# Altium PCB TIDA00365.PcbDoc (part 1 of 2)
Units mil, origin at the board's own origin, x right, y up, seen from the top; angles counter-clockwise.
Board outline 2520 x 2690 mil, 4 copper layers (Top Layer, Mid Layer, GND Layer, Bottom Layer), stack 69.2 mil thick; 170 components, 86 nets, 427 pads, 370 vias.
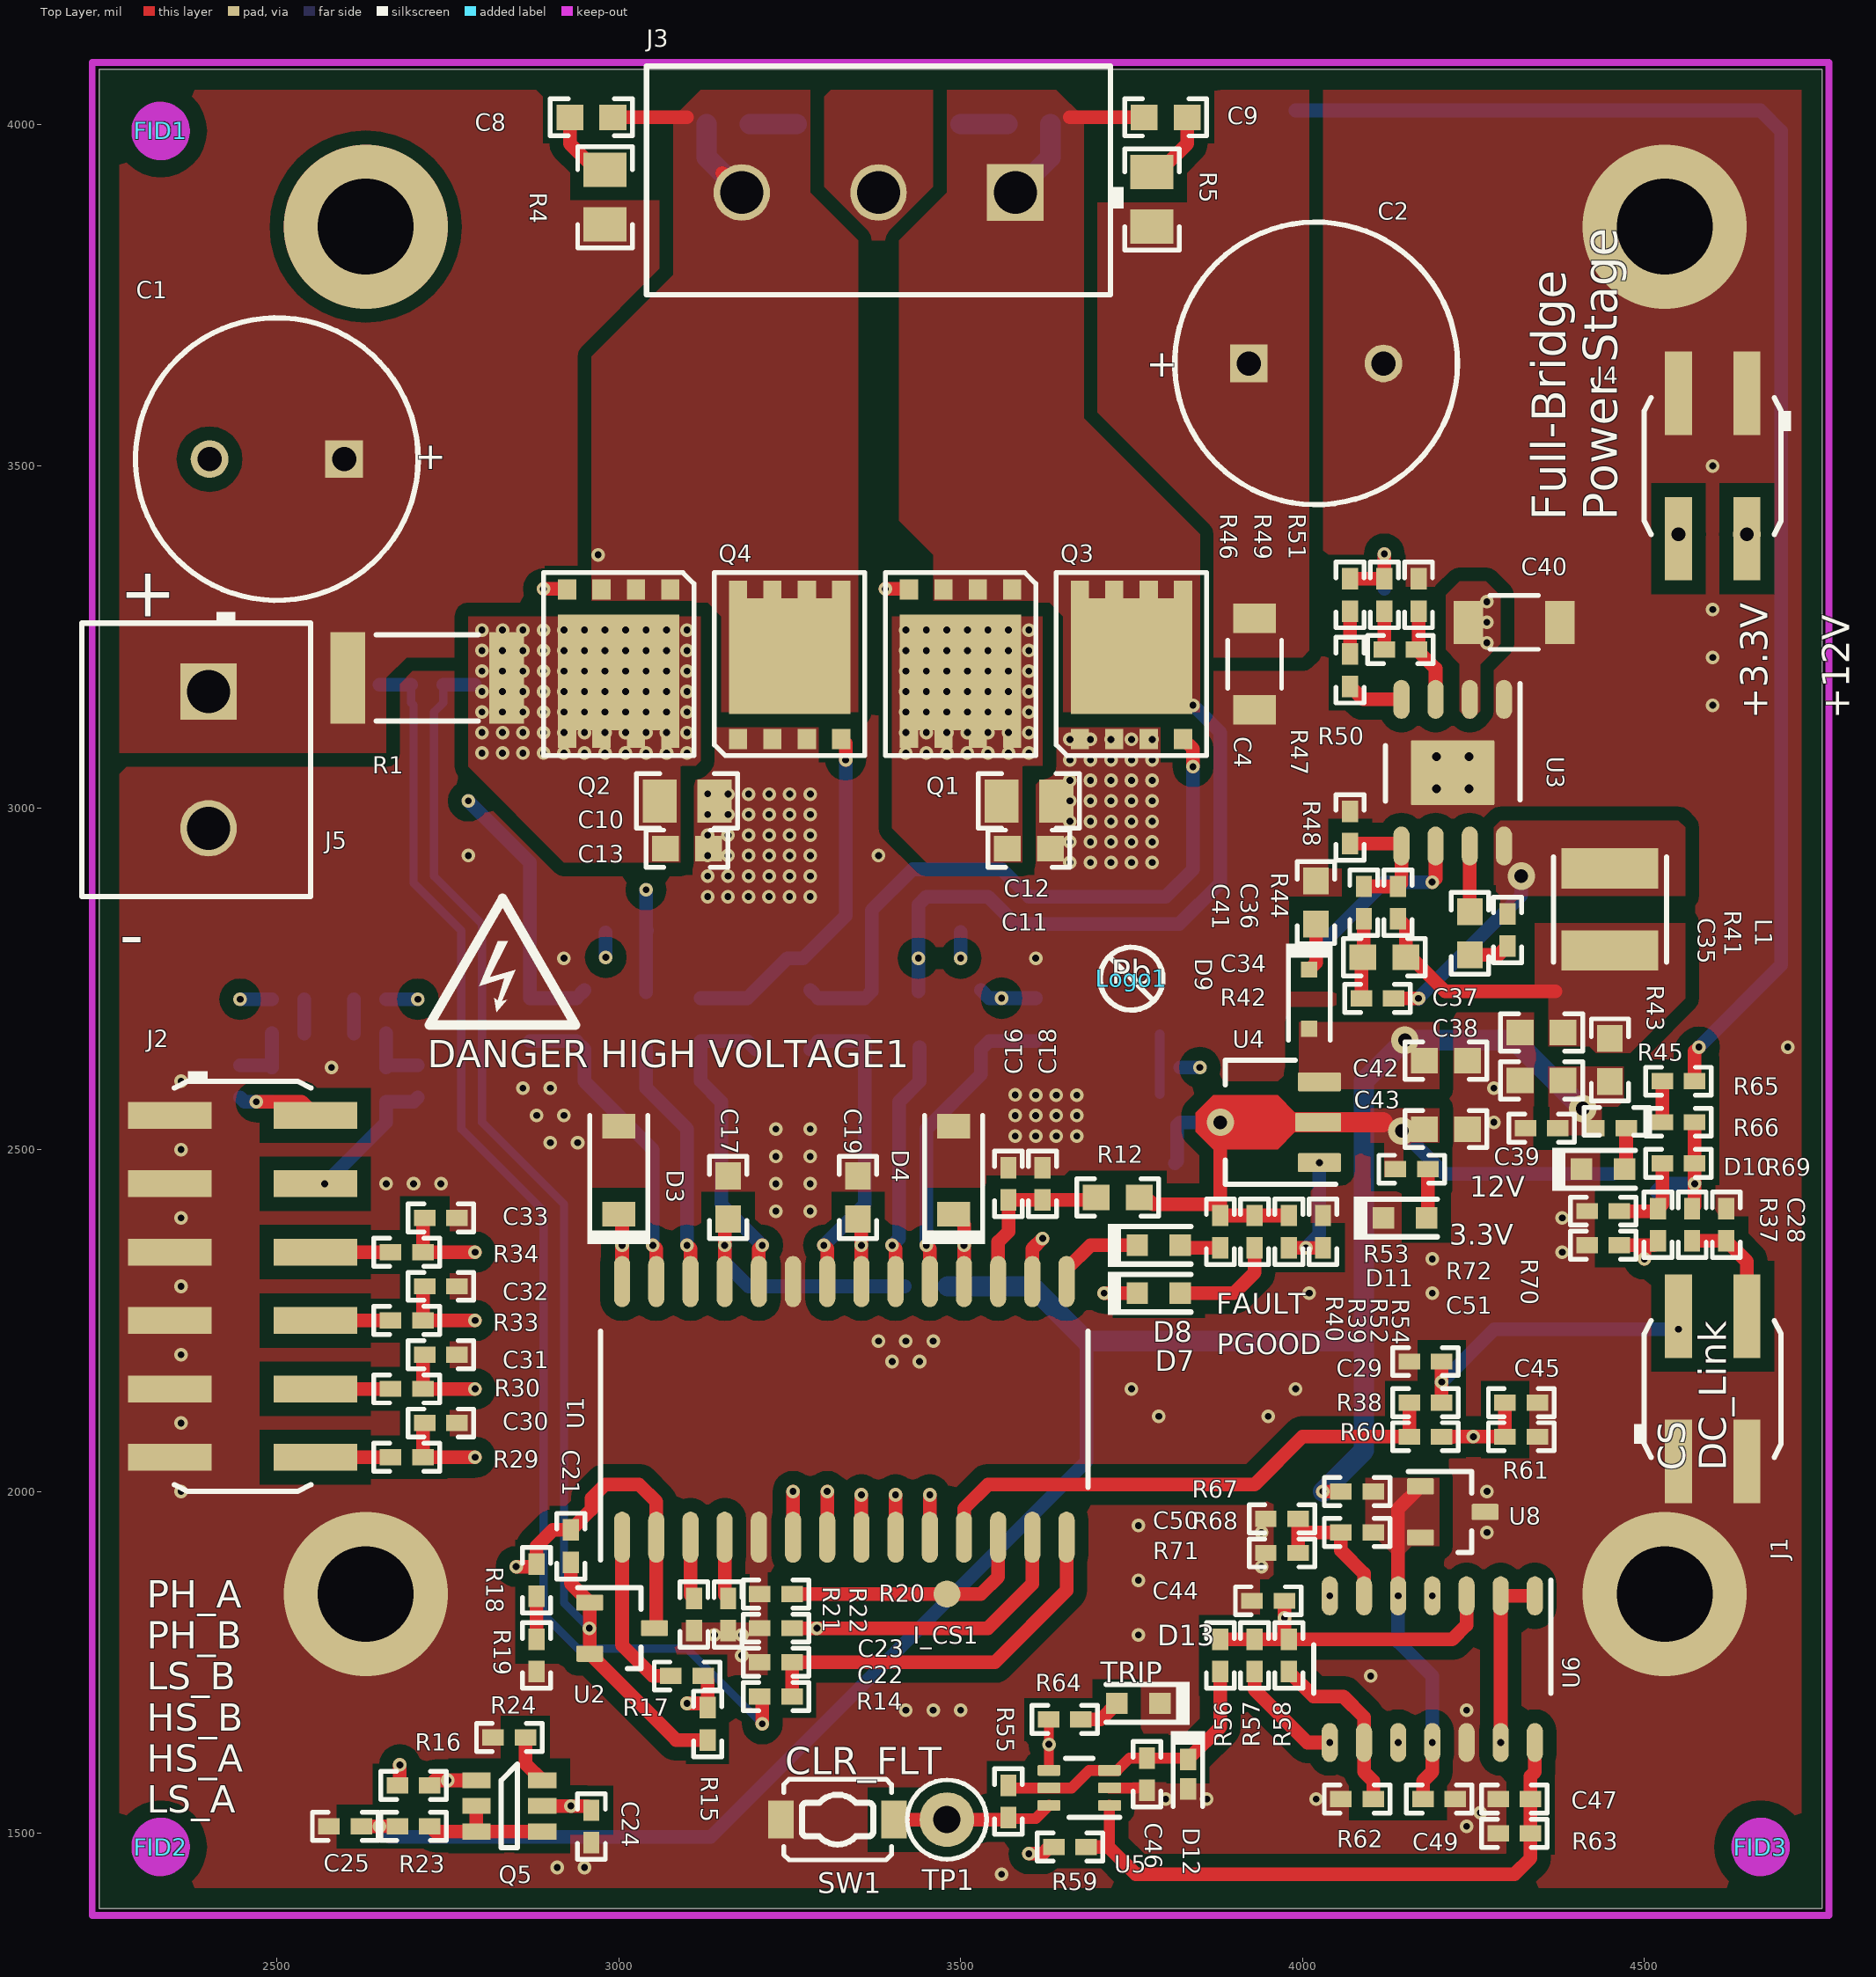
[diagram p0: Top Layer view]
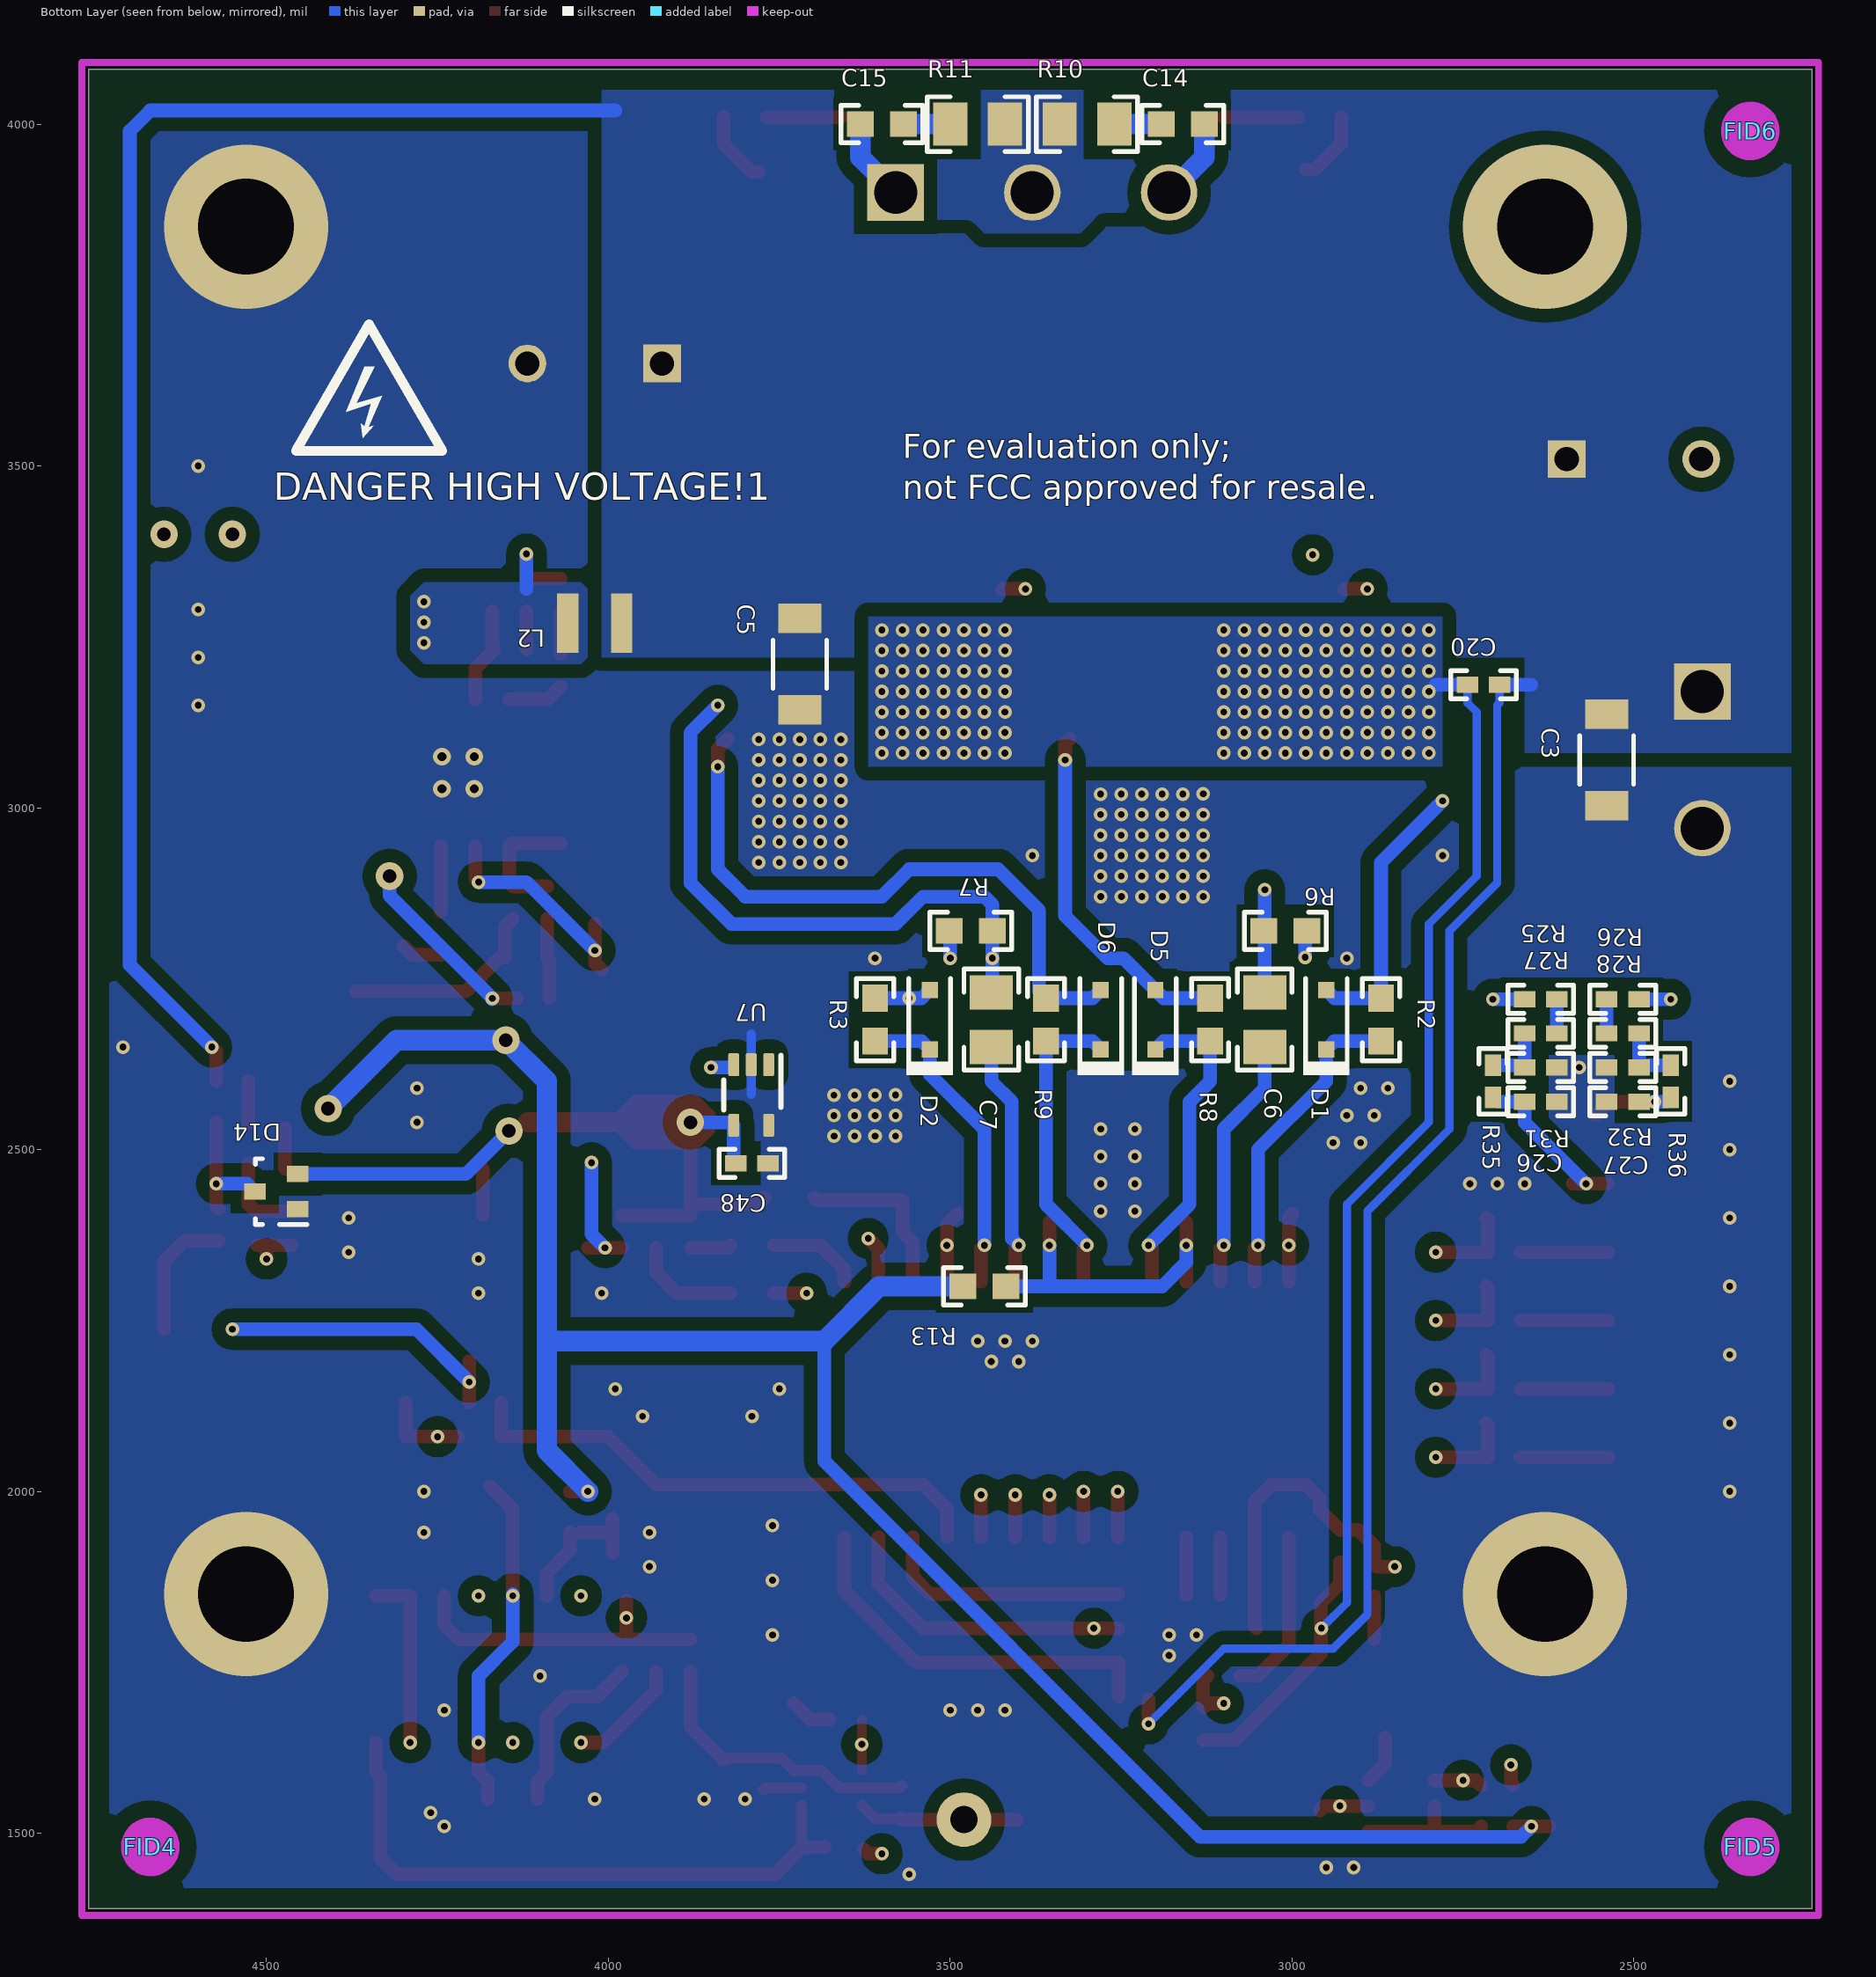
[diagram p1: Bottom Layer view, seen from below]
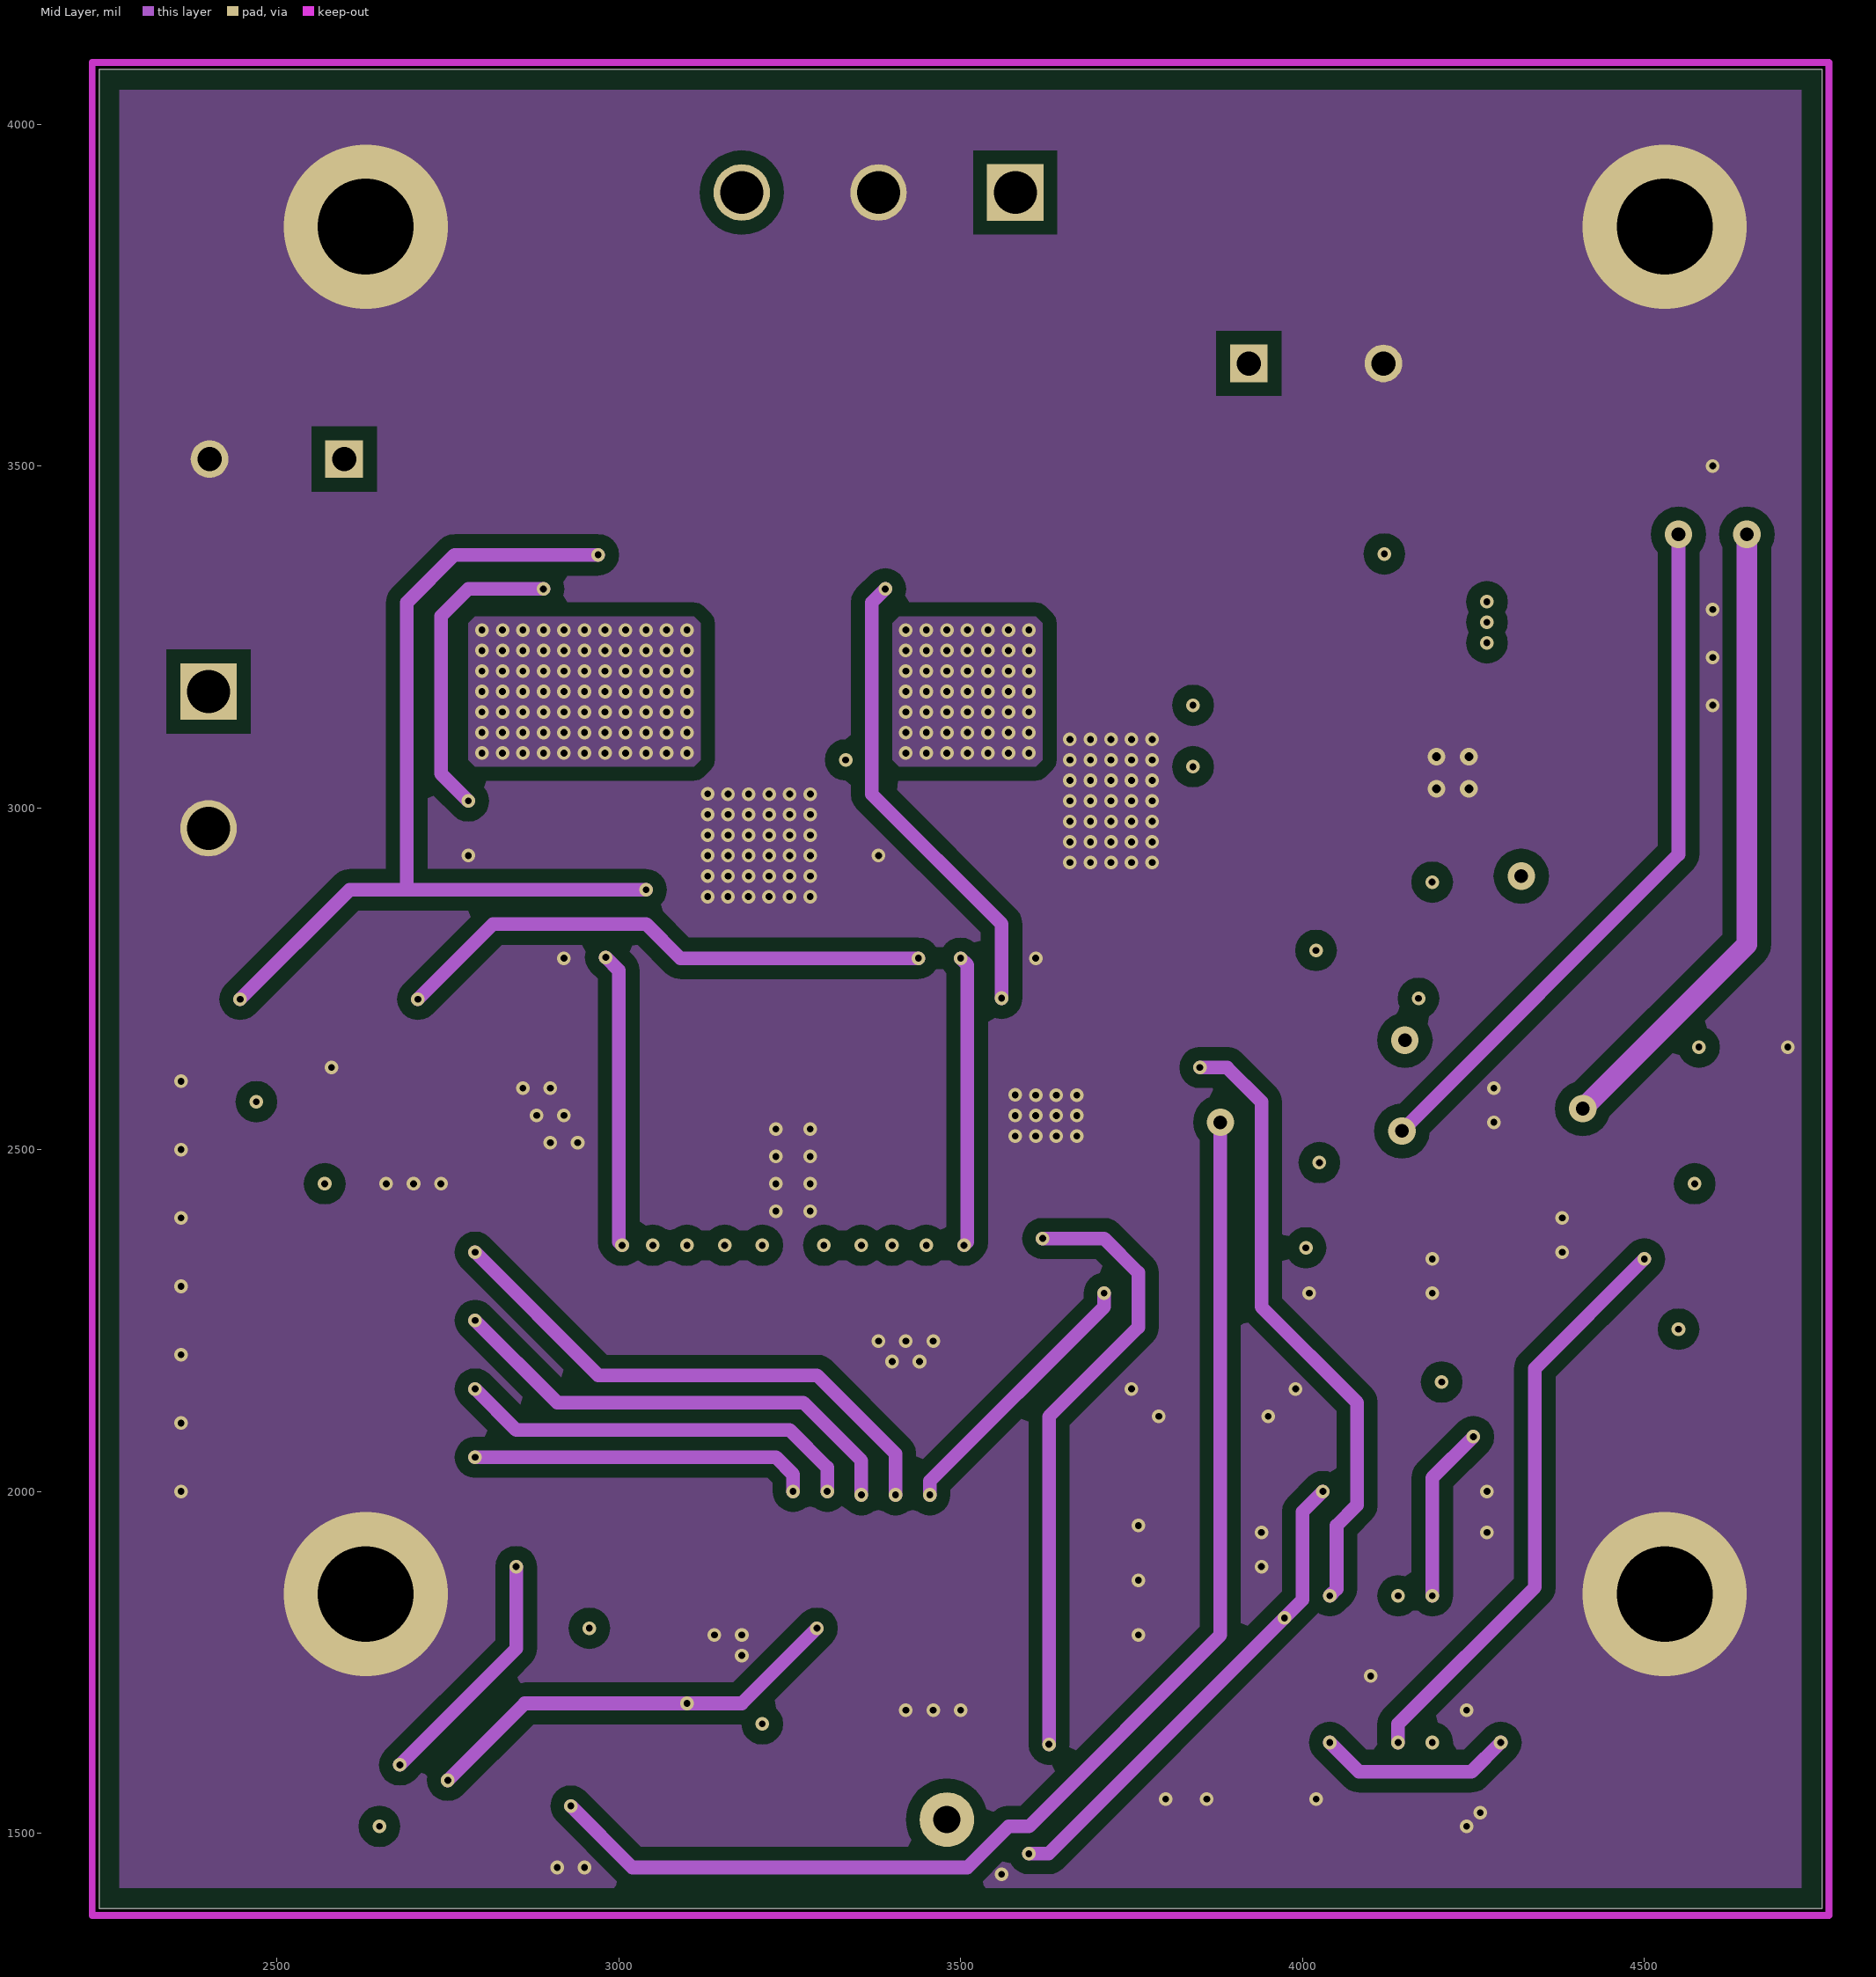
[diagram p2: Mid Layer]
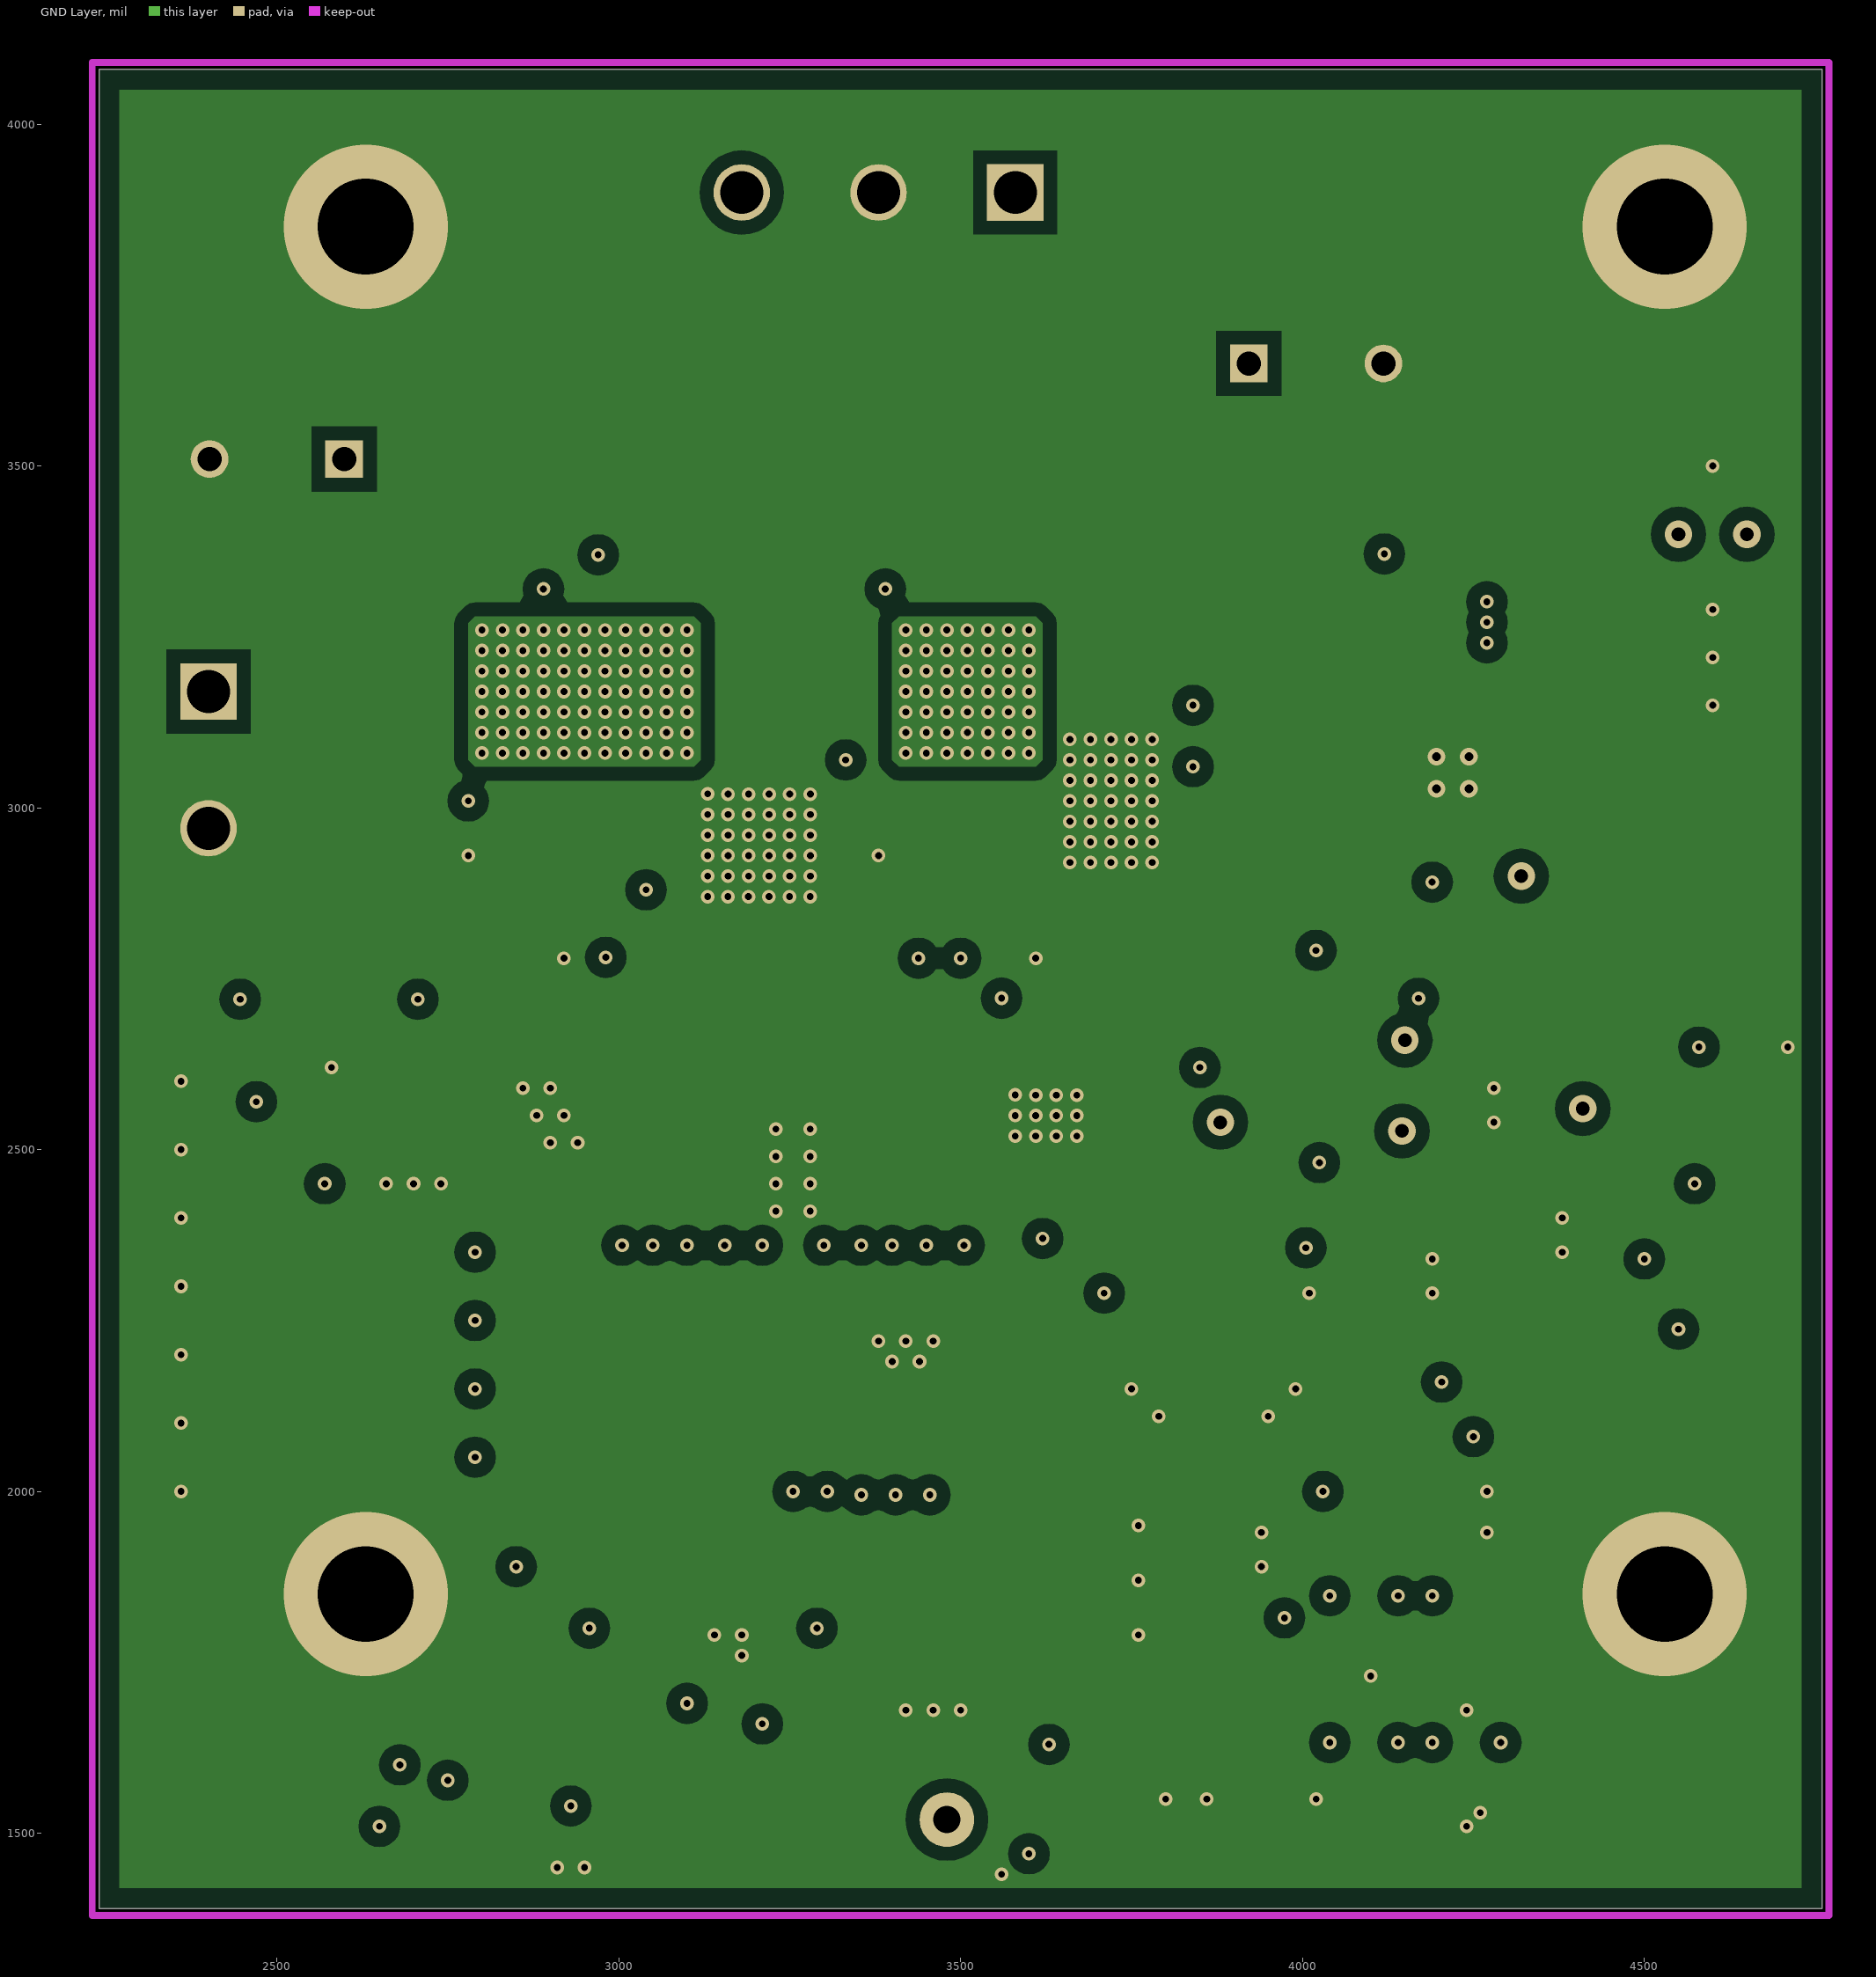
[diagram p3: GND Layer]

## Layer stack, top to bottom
Top Solder: solder mask 0.4, Solder Resist, Dk 3.5
Top Layer: signal copper 2.8
Dielectric: prepreg 12, FR-4, Dk 4.2
Mid Layer: signal copper 2.8
Dielectric: core 34, FR-4, Dk 4.2
GND Layer: signal copper 2.8
Dielectric: prepreg 12, FR-4, Dk 4.2
Bottom Layer: signal copper 2.8
Solder Side: solder mask 0.4, Solder Resist, Dk 3.5

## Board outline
2240,1390 2240,4080 4760,4080 4760,1390

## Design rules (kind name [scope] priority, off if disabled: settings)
AcuteAngle [All] p1: minimum=4.50000000000000E+0001 checktracksonly=FALSE
AssemblyTestPointUsage [All] p1: valid=2
Clearance Clearance_Keepouts [((IsTrack Or IsArc) And Not InPoly) And IsFree and IsKeepOut vs ((IsTrack Or IsArc) And Not InPoly) And IsFree and IsKeepOut] p1: gap=10
Clearance Clearance_BoardEdge_MountingHoles [OnCopper and InComponentClass('Mounting Holes') vs IsKeepOut] p2: gap=10
Clearance Clearance_BoardEdge_Poly [OnCopper and InPoly vs IsKeepOut] p3: gap=25
Clearance Clearance_BoardEdge [OnCopper and Not InComponentClass('Logo') and not InComponentClass('FiducialMark') and not InRegion(1000,500,4000,800) and Not IsKeepout vs IsKeepOut] p4: gap=25
Clearance Clearance_Poly [InPolygon] p5: gap=20
Clearance [All] p6: gap=8
ComponentClearance ComponentClearance_MountingHoles_FiducialMarks [InComponentClass('Mounting Holes') vs InComponentClass('FiducialMark')] p1: gap=20 collisioncheckmode=3 verticalgap=10 showdistances=FALSE
ComponentClearance ComponentClearance_Shunt [InComponentClass('Header') vs InComponentClass('Shunt')] p2: gap=0 collisioncheckmode=3 verticalgap=0 showdistances=FALSE
ComponentClearance ComponentClearance_Logo [InComponentClass('Logo')] p3: gap=10 collisioncheckmode=3 verticalgap=10 showdistances=FALSE
ComponentClearance ComponentClearance_ScrewToNut [(HasFootprint('NY PMS 440 0025 PH')) vs (HasFootprint('Keystone_1902C'))] p4: gap=5 collisioncheckmode=3 verticalgap=10 showdistances=FALSE
ComponentClearance ComponentClearance_MountingHoles [InComponentClass('Mounting Holes')] p5: gap=20 collisioncheckmode=3 verticalgap=100000 showdistances=FALSE
ComponentClearance ComponentClearance_SmallPassives [HasFootprint('0201*') or HasFootprint('0402*') or HasFootprint('0508') or HasFootprint('0603*') or HasFootprint('0612') or HasFootprint('0805*') or HasFootprint('0815*') or HasFootprint('0830*') or HasFootprint('1206*') or HasFootprint('1210*') or HasFootprint('1808*') or HasFootprint('1812*') or HasFootprint('1825*') or HasFootprint('2010*') or HasFootprint('2220*') or HasFootprint('2225*') or HasFootprint('2512*') or HasFootprint('2728*') or HasFootprint('3518*') vs HasFootprint('0201*') or HasFootprint('0402*') or HasFootprint('0508') or HasFootprint('0603*') or HasFootprint('0612') or HasFootprint('0805*') or HasFootprint('0815*') or HasFootprint('0830*') or HasFootprint('1206*') or HasFootprint('1210*') or HasFootprint('1808*') or HasFootprint('1812*') or HasFootprint('1825*') or HasFootprint('2010*') or HasFootprint('2220*') or HasFootprint('2225*') or HasFootprint('2512*') or HasFootprint('2728*') or HasFootprint('3518*')] p6: gap=20 collisioncheckmode=3 verticalgap=10 showdistances=FALSE
ComponentClearance ComponentClearance_THtoSMT [IsThruComponent vs IsSMTComponent] p7: gap=20 collisioncheckmode=3 verticalgap=30 showdistances=FALSE
ComponentClearance ComponentClearance_THtoTH [IsThruComponent vs IsThruComponent] p8: gap=20 collisioncheckmode=3 verticalgap=30 showdistances=FALSE
ComponentClearance [All] p9: gap=25 collisioncheckmode=3 verticalgap=10 showdistances=FALSE
DiffPairsRouting [All] p1: maxlimit=100 minlimit=10 mostfreqgap=10 toplayer_minwidth=15 toplayer_maxwidth=15 toplayer_prefwidth=15 midlayer1_minwidth=15 midlayer1_maxwidth=15 midlayer1_prefwidth=15 midlayer2_minwidth=15 midlayer2_maxwidth=15 midlayer2_prefwidth=15 bottomlayer_minwidth=15 bottomlayer_maxwidth=15 bottomlayer_prefwidth=15 maxuncoupledlength=1000
FabricationTestPointUsage TestPointUsage [All] p1: valid=2 allowmultiple=FALSE
FabricationTestpoint Testpoint [All] p1: side=3 testpointundercomponent=TRUE minsize=40 maxsize=100 preferedsize=60 minholesize=0 maxholesize=40 preferedholesize=32 testpointgrid=1 allowsidetop=TRUE allowsidebottom=TRUE usegrid=TRUE gridtolerance=0.01
FanoutControl Fanout_LCC [IsLCC] p1: bgadir=Out bgaviamode=Centered fanoutstyle=Auto fanoutdirection=Alternating viagrid=1 // Fanout_LCC (Default Rule)
FanoutControl Fanout_BGA [IsBGA] p2: bgadir=Out bgaviamode=Centered fanoutstyle=Auto fanoutdirection=Alternating viagrid=1 // Fanout_BGA (Default Rule)
FanoutControl Fanout_Default [All] p4: bgadir=Out bgaviamode=Centered fanoutstyle=Auto fanoutdirection=Alternating viagrid=1 // Fanout_Default (Default Rule)
FanoutControl Fanout_Small [(CompPinCount < 5)] p5: bgadir=Out bgaviamode=Centered fanoutstyle=Auto fanoutdirection=OutThenIn viagrid=1 // Fanout_Small (Default Rule)
Height [All] p1: minheight=0 maxheight=1100 prefheight=500
HoleSize [All] p1: absolutevalues=TRUE maxlimit=251 minlimit=8 maxpercent=80.000 minpercent=20.000
MinimumAnnularRing MinimumAnnularRing_ThermalPadVias [IsVia and InAnyComponent] p1: minimumring=6
MinimumAnnularRing [All] p2: minimumring=4
MinimumSolderMaskSliver MinimumSolderMaskSliver_Logo [InComponentClass('Logo') vs InComponentClass('Logo')] p1: minsoldermaskwidth=0.7
MinimumSolderMaskSliver [All] p2: minsoldermaskwidth=0
PlaneConnect [All] p1: planeconnectstyle=Relief reliefexpansion=10 reliefentries=4 reliefconductorwidth=10 reliefairgap=10
PolygonConnect PolygonConnect_59 [All vs IsNamedPolygon('GND_L04_P043')] p1: connectstyle=Direct reliefconductorwidth=10 reliefentries=4 polygonreliefangle="90 Angle" airgapwidth=10
PolygonConnect PolygonConnect_58 [All vs IsNamedPolygon('PROT_VTH_L01_P044')] p2: connectstyle=Direct reliefconductorwidth=10 reliefentries=4 polygonreliefangle="90 Angle" airgapwidth=10
PolygonConnect PolygonConnect_57 [All vs IsNamedPolygon('NONET_L04_P125')] p3: connectstyle=Direct reliefconductorwidth=10 reliefentries=4 polygonreliefangle="90 Angle" airgapwidth=10
PolygonConnect PolygonConnect_56 [All vs IsNamedPolygon('NONET_L04_P127')] p4: connectstyle=Direct reliefconductorwidth=10 reliefentries=4 polygonreliefangle="90 Angle" airgapwidth=10
PolygonConnect PolygonConnect_55 [All vs IsNamedPolygon('HS_CSN_2_L03_P049')] p5: connectstyle=Direct reliefconductorwidth=10 reliefentries=4 polygonreliefangle="90 Angle" airgapwidth=10
PolygonConnect PolygonConnect_54 [All vs IsNamedPolygon('HS_CSN_2_L03_P048')] p6: connectstyle=Direct reliefconductorwidth=10 reliefentries=4 polygonreliefangle="90 Angle" airgapwidth=10
PolygonConnect PolygonConnect_53 [All vs IsNamedPolygon('HS_CSN_2_L02_P050')] p7: connectstyle=Direct reliefconductorwidth=10 reliefentries=4 polygonreliefangle="90 Angle" airgapwidth=10
PolygonConnect PolygonConnect_52 [All vs IsNamedPolygon('HS_CSN_2_L02_P051')] p8: connectstyle=Direct reliefconductorwidth=10 reliefentries=4 polygonreliefangle="90 Angle" airgapwidth=10
PolygonConnect PolygonConnect_51 [All vs IsNamedPolygon('NETC32_1_L01_P052')] p9: connectstyle=Direct reliefconductorwidth=10 reliefentries=4 polygonreliefangle="90 Angle" airgapwidth=10
PolygonConnect PolygonConnect_50 [All vs IsNamedPolygon('HS_CSN_2_L04_P053')] p10: connectstyle=Direct reliefconductorwidth=10 reliefentries=4 polygonreliefangle="90 Angle" airgapwidth=10
PolygonConnect PolygonConnect_49 [All vs IsNamedPolygon('HS_CSN_2_L04_P053')] p11: connectstyle=Direct reliefconductorwidth=10 reliefentries=4 polygonreliefangle="90 Angle" airgapwidth=10
PolygonConnect PolygonConnect_48 [All vs IsNamedPolygon('HS_CSN_2_L01_P054')] p12: connectstyle=Direct reliefconductorwidth=10 reliefentries=4 polygonreliefangle="90 Angle" airgapwidth=10
PolygonConnect PolygonConnect_47 [All vs IsNamedPolygon('PHASEB+_L01_P056')] p13: connectstyle=Direct reliefconductorwidth=10 reliefentries=4 polygonreliefangle="90 Angle" airgapwidth=10
PolygonConnect PolygonConnect_46 [All vs IsNamedPolygon('HS_CSN_2_L01_P057')] p14: connectstyle=Direct reliefconductorwidth=10 reliefentries=4 polygonreliefangle="90 Angle" airgapwidth=10
PolygonConnect PolygonConnect_45 [All vs IsNamedPolygon('HS_CSP_2_L01_P058')] p15: connectstyle=Direct reliefconductorwidth=10 reliefentries=4 polygonreliefangle="90 Angle" airgapwidth=10
PolygonConnect PolygonConnect_44 [All vs IsNamedPolygon('PHASEB+_L01_P056')] p16: connectstyle=Direct reliefconductorwidth=10 reliefentries=4 polygonreliefangle="90 Angle" airgapwidth=10
PolygonConnect PolygonConnect_43 [All vs IsNamedPolygon('PHASEB-_L01_P055')] p17: connectstyle=Direct reliefconductorwidth=10 reliefentries=4 polygonreliefangle="90 Angle" airgapwidth=10
PolygonConnect PolygonConnect_42 [All vs IsNamedPolygon('GND_L02_P079')] p18: connectstyle=Direct reliefconductorwidth=10 reliefentries=4 polygonreliefangle="90 Angle" airgapwidth=10
PolygonConnect PolygonConnect_41 [All vs IsNamedPolygon('GND_L04_P077')] p19: connectstyle=Direct reliefconductorwidth=10 reliefentries=4 polygonreliefangle="90 Angle" airgapwidth=10
PolygonConnect PolygonConnect_40 [All vs IsNamedPolygon('GND_L01_P115')] p20: connectstyle=Direct reliefconductorwidth=10 reliefentries=4 polygonreliefangle="90 Angle" airgapwidth=10
PolygonConnect PolygonConnect_39 [All vs IsNamedPolygon('HS_CSP_2_L04_P063')] p21: connectstyle=Direct reliefconductorwidth=10 reliefentries=4 polygonreliefangle="90 Angle" airgapwidth=10
PolygonConnect PolygonConnect_38 [All vs IsNamedPolygon('HS_CSP_2_L04_P063')] p22: connectstyle=Direct reliefconductorwidth=10 reliefentries=4 polygonreliefangle="90 Angle" airgapwidth=10
PolygonConnect PolygonConnect_37 [All vs IsNamedPolygon('HS_CSP_2_L04_P063')] p23: connectstyle=Direct reliefconductorwidth=10 reliefentries=4 polygonreliefangle="90 Angle" airgapwidth=10
PolygonConnect PolygonConnect_36 [All vs IsNamedPolygon('HS_CSN_2_L04_P072')] p24: connectstyle=Direct reliefconductorwidth=10 reliefentries=4 polygonreliefangle="90 Angle" airgapwidth=10
PolygonConnect PolygonConnect_35 [All vs IsNamedPolygon('HS_CSP_2_L01_P061')] p25: connectstyle=Direct reliefconductorwidth=10 reliefentries=4 polygonreliefangle="90 Angle" airgapwidth=10
PolygonConnect PolygonConnect_34 [All vs IsNamedPolygon('Mid Layer-No Net')] p26: connectstyle=Direct reliefconductorwidth=10 reliefentries=4 polygonreliefangle="90 Angle" airgapwidth=10
PolygonConnect PolygonConnect_33 [All vs IsNamedPolygon('NETC28_1_L01_P073')] p27: connectstyle=Direct reliefconductorwidth=10 reliefentries=4 polygonreliefangle="90 Angle" airgapwidth=10
PolygonConnect PolygonConnect_32 [All vs IsNamedPolygon('Bottom Layer-No Net 4')] p28: connectstyle=Direct reliefconductorwidth=10 reliefentries=4 polygonreliefangle="90 Angle" airgapwidth=10
PolygonConnect PolygonConnect_31 [All vs IsNamedPolygon('GND Layer-No Net')] p29: connectstyle=Direct reliefconductorwidth=10 reliefentries=4 polygonreliefangle="90 Angle" airgapwidth=10
PolygonConnect PolygonConnect_30 [All vs IsNamedPolygon('Top Layer-No Net 16')] p30: connectstyle=Direct reliefconductorwidth=10 reliefentries=4 polygonreliefangle="90 Angle" airgapwidth=10
PolygonConnect PolygonConnect_29 [All vs IsNamedPolygon('Top Layer-No Net 15')] p31: connectstyle=Direct reliefconductorwidth=10 reliefentries=4 polygonreliefangle="90 Angle" airgapwidth=10
PolygonConnect PolygonConnect_28 [All vs IsNamedPolygon('Top Layer-No Net 14')] p32: connectstyle=Direct reliefconductorwidth=10 reliefentries=4 polygonreliefangle="90 Angle" airgapwidth=10
PolygonConnect PolygonConnect_27 [All vs IsNamedPolygon('Top Layer-No Net 13')] p33: connectstyle=Direct reliefconductorwidth=10 reliefentries=4 polygonreliefangle="90 Angle" airgapwidth=10
PolygonConnect PolygonConnect_26 [All vs IsNamedPolygon('NETL5_1_L01_P067')] p34: connectstyle=Direct reliefconductorwidth=10 reliefentries=4 polygonreliefangle="90 Angle" airgapwidth=10
PolygonConnect PolygonConnect_25 [All vs IsNamedPolygon('+12V_L01_P064')] p35: connectstyle=Direct reliefconductorwidth=10 reliefentries=4 polygonreliefangle="90 Angle" airgapwidth=10
PolygonConnect PolygonConnect_24 [All vs IsNamedPolygon('+12V_L01_P074')] p36: connectstyle=Direct reliefconductorwidth=10 reliefentries=4 polygonreliefangle="90 Angle" airgapwidth=10
PolygonConnect PolygonConnect_23 [All vs IsNamedPolygon('Bottom Layer-No Net 3')] p37: connectstyle=Direct reliefconductorwidth=10 reliefentries=4 polygonreliefangle="90 Angle" airgapwidth=10
PolygonConnect PolygonConnect_22 [All vs IsNamedPolygon('Bottom Layer-No Net 2')] p38: connectstyle=Direct reliefconductorwidth=10 reliefentries=4 polygonreliefangle="90 Angle" airgapwidth=10
PolygonConnect PolygonConnect_21 [All vs IsNamedPolygon('Bottom Layer-No Net 1')] p39: connectstyle=Direct reliefconductorwidth=10 reliefentries=4 polygonreliefangle="90 Angle" airgapwidth=10
PolygonConnect PolygonConnect_20 [All vs IsNamedPolygon('Bottom Layer-No Net')] p40: connectstyle=Direct reliefconductorwidth=10 reliefentries=4 polygonreliefangle="90 Angle" airgapwidth=10
PolygonConnect PolygonConnect_19 [All vs IsNamedPolygon('Bottom Layer-No Net 1')] p41: connectstyle=Direct reliefconductorwidth=10 reliefentries=4 polygonreliefangle="90 Angle" airgapwidth=10
PolygonConnect PolygonConnect_18 [All vs IsNamedPolygon('GND_L03_P078')] p42: connectstyle=Direct reliefconductorwidth=10 reliefentries=4 polygonreliefangle="90 Angle" airgapwidth=10
PolygonConnect PolygonConnect_17 [All vs IsNamedPolygon('GND_L03_P078')] p43: connectstyle=Direct reliefconductorwidth=10 reliefentries=4 polygonreliefangle="90 Angle" airgapwidth=10
PolygonConnect PolygonConnect_16 [All vs IsNamedPolygon('GND_L03_P078')] p44: connectstyle=Direct reliefconductorwidth=10 reliefentries=4 polygonreliefangle="90 Angle" airgapwidth=10
PolygonConnect PolygonConnect_15 [All vs IsNamedPolygon('GND_L03_P078')] p45: connectstyle=Direct reliefconductorwidth=10 reliefentries=4 polygonreliefangle="90 Angle" airgapwidth=10
PolygonConnect PolygonConnect_14 [All vs IsNamedPolygon('GND_L03_P078')] p46: connectstyle=Direct reliefconductorwidth=10 reliefentries=4 polygonreliefangle="90 Angle" airgapwidth=10
PolygonConnect PolygonConnect_13 [All vs IsNamedPolygon('NETC32_1_L04_P065')] p47: connectstyle=Direct reliefconductorwidth=10 reliefentries=4 polygonreliefangle="90 Angle" airgapwidth=10
PolygonConnect PolygonConnect_12 [All vs IsNamedPolygon('NETL5_1_L01_P067')] p48: connectstyle=Direct reliefconductorwidth=10 reliefentries=4 polygonreliefangle="90 Angle" airgapwidth=10
PolygonConnect PolygonConnect_11 [All vs IsNamedPolygon('+3V3_L01_P045')] p49: connectstyle=Direct reliefconductorwidth=10 reliefentries=4 polygonreliefangle="90 Angle" airgapwidth=10
PolygonConnect PolygonConnect_10 [All vs IsNamedPolygon('+3V3_L01_P045')] p50: connectstyle=Direct reliefconductorwidth=10 reliefentries=4 polygonreliefangle="90 Angle" airgapwidth=10
PolygonConnect PolygonConnect_9 [All vs IsNamedPolygon('NETC32_1_L04_P065')] p51: connectstyle=Direct reliefconductorwidth=10 reliefentries=4 polygonreliefangle="90 Angle" airgapwidth=10
PolygonConnect PolygonConnect_8 [All vs IsNamedPolygon('NETL5_1_L01_P067')] p52: connectstyle=Direct reliefconductorwidth=10 reliefentries=4 polygonreliefangle="90 Angle" airgapwidth=10
PolygonConnect PolygonConnect_7 [All vs IsNamedPolygon('NETC28_1_L01_P073')] p53: connectstyle=Direct reliefconductorwidth=10 reliefentries=4 polygonreliefangle="90 Angle" airgapwidth=10
PolygonConnect PolygonConnect_6 [All vs IsNamedPolygon('+3V3_L01_P045')] p54: connectstyle=Direct reliefconductorwidth=10 reliefentries=4 polygonreliefangle="90 Angle" airgapwidth=10
PolygonConnect PolygonConnect_5 [All vs IsNamedPolygon('+3V3_L01_P045')] p55: connectstyle=Direct reliefconductorwidth=10 reliefentries=4 polygonreliefangle="90 Angle" airgapwidth=10
PolygonConnect PolygonConnect_4 [All vs IsNamedPolygon('Top Layer-No Net 3')] p56: connectstyle=Direct reliefconductorwidth=10 reliefentries=4 polygonreliefangle="90 Angle" airgapwidth=10
PolygonConnect PolygonConnect_3 [All vs IsNamedPolygon('Top Layer-No Net 1')] p57: connectstyle=Direct reliefconductorwidth=10 reliefentries=4 polygonreliefangle="90 Angle" airgapwidth=10
PolygonConnect PolygonConnect_2 [All vs IsNamedPolygon('+12V_L01_P064')] p58: connectstyle=Direct reliefconductorwidth=10 reliefentries=4 polygonreliefangle="90 Angle" airgapwidth=10
PolygonConnect PolygonConnect_1 [All vs IsNamedPolygon('GND_L03_P078')] p59: connectstyle=Direct reliefconductorwidth=10 reliefentries=4 polygonreliefangle="90 Angle" airgapwidth=10
PolygonConnect [All] p60: connectstyle=Direct reliefconductorwidth=10 reliefentries=4 polygonreliefangle="90 Angle" airgapwidth=10
RoutingVias ThermalPadVias [IsVia and InAnyComponent] p1: holewidth=10 width=20 viastyle="Through Hole" minholewidth=5 minwidth=15 maxholewidth=25 maxwidth=45
RoutingVias [All] p2: holewidth=10 width=20 viastyle="Through Hole" minholewidth=5 minwidth=10 maxholewidth=200 maxwidth=300
SilkToBoardRegionClearance [Not ((IsComment or IsDesignator) And (Hide <> 'False')) and not InRegion(1000,500,4000,800)] p1:
SilkToSilkClearance SilkToSilkClearance_Pb-FreeLogo [(HasFootprint('Pb-Free_Overlay_Medium') OR HasFootprint('Pb-Free_Overlay_Small')) vs (HasFootprint('Pb-Free_Overlay_Medium') OR HasFootprint('Pb-Free_Overlay_Small'))] p1: silktosilkclearance=0
SilkToSilkClearance [All] p2: silktosilkclearance=0
SilkToSolderMaskClearance SilkToComonentPadClearance [IsPad and InAnycomponent] p1: minsilkscreentomaskgap=0 clearancetoexposedcopper=TRUE
SilkToSolderMaskClearance "Silk to Solder Mask Opening" [All] p2: minsilkscreentomaskgap=0 clearancetoexposedcopper=FALSE
SolderMaskExpansion [All] p1: expansion=1.97
Width [All] p1: maxlimit=200 minlimit=5 preferedwidth=20 checkconnectedcopper=TRUE
14 further rules are at their usual default settings.

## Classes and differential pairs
component class FiducialMark: FID1 FID2 FID3 FID4 FID5 FID6
component class TIDA00365_Interfaces: C3 C26 C27 C28 C30 C31 C32 C33 D1 D7 J2 J3 R8 R28 R29 R30 R31 R32 R33 R34 R35 R36 R37 R38 R39 R40 R53
component class "TIDA00365_Power Supply": 4V 12V C34 C35 C37 C38 C40 C41 C42 C43 C49 D1 D3 D11 J1 J4 L1 L2 R39 R41 R42 R43 R44 R45 R46 R47 R48 R49 R50 R52 R53 R54 U2 U4
component class "TIDA00365_Full Bridge": C2 C3 C4 C5 C6 C7 C9 C11 C12 C13 C14 C15 C16 C17 C18 C19 C20 C21 C22 C23 C24 C25 C45 C48 D1 D2 D3 D7 D11 D12 D14 I_CS1 Q1 Q2 Q3 Q4 Q5 R1 R2 R3 R4 R8 R12 R13 R15 R16 R20 R22 R23 R24 R34 R37 R39 R54 R58 R59 R62 R63 R65 R68 R70 U2 U7
component class TIDA00365_Protections: C1 C44 C45 C46 C47 C48 C49 C50 C51 D12 D13 D14 R1 R8 R17 R55 R56 R57 R58 R59 R60 R61 R62 R63 R65 R66 R68 R70 R71 R72 R? SW1 TP1 U5 U6 U7 U8
component class Header: J1 J4 J5
component class TIDA00365_Hardware: "DANGER HIGH VOLTAGE1" "DANGER HIGH VOLTAGE!1" FID1 FID2 FID3 FID4 FID5 FID6 Logo1 Logo2

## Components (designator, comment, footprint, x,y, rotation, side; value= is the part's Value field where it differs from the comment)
C1 "860040875005" WCAP-ATUL_1000x2500 2500,3510 r180 top
C2 "860040875005" WCAP-ATUL_1000x2500 4020,3650 r0 top
C3 "C3216X7S2A335M160AB" 1206_190 2540,3070 r270 bottom
C4 "C3216X7S2A335M160AB" 1206_190 3930,3210 r270 top
C5 "C3216X7S2A335M160AB" 1206_190 3720,3210 r270 bottom
C6 "C2012X7R2A104K125AA" 0805_HV 3040,2690 r90 bottom
C7 "C2012X7R2A104K125AA" 0805_HV 3440,2690 r90 bottom
C8 "06031C222JAT2A" 0603 2960,4010 r0 top
C9 "06031C222JAT2A" 0603 3800,4010 r180 top
C10 "C2012X7S2A105K125AB" 0805_HV 3100,3010 r0 top
C11 "06031C103KAT2A" 0603 3600,2940 r0 top
C12 "C2012X7S2A105K125AB" 0805_HV 3600,3010 r0 top
C13 "06031C103KAT2A" 0603 3100,2940 r0 top
C14 "06031C222JAT2A" 0603 3160,4000 r180 bottom
C15 "06031C222JAT2A" 0603 3600,4000 r0 bottom
C16 "885012205031" 0402#1 3570,2450 r90 top
C17 "885012106017" 0603 3160,2430 r270 top
C18 "C1005X7R1E104M050BB" 0402#1 3620,2450 r90 top
C19 "885012106017" 0603 3350,2430 r270 top
C20 "GRM155R72A472KA01D" 0402#1 2720,3180 r0 bottom
C21 "885012205055" 0402#1 2930,1920 r90 top
C22 "885012205055" 0402#1 3230,1750 r0 top
C23 "885012205055" 0402#1 3230,1800 r180 top
C24 "885012205031" 0402#1 2960,1510 r270 top
C25 "885012205031" 0402#1 2600,1510 r180 top
C26 "CC0402KRX7R9BB101" 0402#1 2636.38,2570 r0 bottom
C27 "CC0402KRX7R9BB101" 0402#1 2516.38,2570 r180 bottom
C28 "CC0402KRX7R9BB101" 0402#1 4620,2390 r270 top
C29 "CC0402KRX7R9BB101" 0402#1 4180,2190 r0 top
C30 "CC0402KRX7R9BB101" 0402#1 2740,2100 r0 top
C31 "CC0402KRX7R9BB101" 0402#1 2740,2200 r0 top
C32 "CC0402KRX7R9BB101" 0402#1 2740,2300 r0 top
C33 "CC0402KRX7R9BB101" 0402#1 2740,2400 r0 top
C34 "GRM188R72A332KA01D" 0603 4119.8,2781.3 r180 top
C35 "GRM188R72A104KA35D" 0603 4244.8,2816.3 r270 top
C36 "C1005X7R1E104M050BB" 0402#1 4089.8,2861.3 r90 top
C37 "GRM188R61E475KE11D" 0603 4349.8,2671.3 r180 top
C38 "GRM188R61E475KE11D" 0603 4349.8,2601.3 r180 top
C39 "C1005X7R1E104M050BB" 0402#1 4349.8,2531.3 r180 top
C40 "C3216X7S2A335M160AB" 1206_190 4309.8,3271.3 r0 top
C41 "C1608X5R1C105K" 0603 4019.8,2861.3 r90 top
C42 "C1608X5R1C105K" 0603 4210,2630 r0 top
C43 "C1608X5R1C105K" 0603 4210,2530 r0 top
C44 "C1005X7R1E104M050BB" 0402#1 3950,1840 r180 top
C45 "CC0402KRX7R9BB101" 0402#1 4320,2130 r0 top
C46 "885012205031" 0402#1 3772.65,1586.38 r270 top
C47 "CC0402KRX7R9BB101" 0402#1 4310,1550 r180 top
C48 "C1005X7R1E104M050BB" 0402#1 3790,2480 r180 bottom
C49 "885012205044" 0402#1 4200,1550 r0 top
C50 "885012105016" 0402#1 3970,1960 r180 top
C51 "CC0402KRX7R9BB101" 0402#1 4440,2360 r180 top
D1 "BAS316,115" sod-323 2950,2690 r90 bottom
D2 "BAS316,115" sod-323 3530,2690 r90 bottom
D3 "MMSZ5270BT1G" SOD-123 3000,2470 r90 top
D4 "MMSZ5270BT1G" SOD-123 3490,2470 r90 top
D5 "BAS316,115" sod-323 3200,2690 r90 bottom
D6 "BAS316,115" sod-323 3280,2690 r90 bottom
D7 "150060RS75000" WL-SMCW_RED 3790,2290 r0 top
D8 "150060RS75000" WL-SMCW_RED 3790,2360 r0 top
D9 "BAS316,115" sod-323 4010,2720 r270 top
D10 "150060GS75000" WL-SMCW_GREEN 4439.8,2471.3 r0 top
D11 "150060GS75000" WL-SMCW_GREEN 4150,2400 r0 top
D12 "BZT52C3V9T-7" SOD-523 3832.65,1586.38 r270 top
D13 "150060RS75000" WL-SMCW_RED 3760,1690 r180 top
D14 "BAV99W-7-F" SOT-323 4485.75,2438.6 r0 bottom
"DANGER HIGH VOLTAGE1" "DANGER HIGH VOLTAGE" IEC_HighVoltage_Small 2830,2770 r0 top
"DANGER HIGH VOLTAGE!1" "DANGER HIGH VOLTAGE" IEC_HighVoltage_Small 4350,3610 r180 bottom
FID1 "Fiducial" Fiducial6.4-20 2330,3990 r270 top
FID2 "Fiducial" Fiducial6.4-20 2330,1480 r270 top
FID3 "Fiducial" Fiducial6.4-20 4670,1480 r0 top
FID4 "Fiducial" Fiducial6.4-20 4670,1480 r180 bottom
FID5 "Fiducial" Fiducial6.4-20 2330,1480 r180 bottom
FID6 "Fiducial" Fiducial6.4-20 2330,3990 r180 bottom
I_CS1 "TESTPOINT" TP_SM_1MM 3480,1850 r90 top
J1 "61030421121" Wurth_61030421121 4600,2150 r90 top
J2 "61031221121" Wurth_61031221121 2450,2300 r0 top
J3 "691311500103" Wurth_691311500103 3380,3900 r180 top
J4 "61030421121" Wurth_61030421121 4600,3500 r270 top
J5 "691311500002" Wurth_691311500002 2400,3070 r270 top
L1 "74404041101" WE-LQS_4012 4449.8,2851.3 r270 top
L2 "74479887310" WE-PMI_1008 4020,3270 r0 bottom
Logo1 "Pb-Free Symbol" Pb-Free_Overlay_Small 3750,2750 r0 top
Logo2 "FCC disclaimer" FCC_disclaimer 1970,2060 r270 bottom
Q1 "CSD19534Q5A" TRANS_NexFET_Q5A 3500,3210 r270 top
Q2 "CSD19534Q5A" TRANS_NexFET_Q5A 3000,3210 r270 top
Q3 "CSD19534Q5A" TRANS_NexFET_Q5A 3750,3210 r90 top
Q4 "CSD19534Q5A" TRANS_NexFET_Q5A 3250,3210 r90 top
Q5 "DMMT5551-7-F" SOT-26 2840,1540 r0 top
R1 "CRA2512-FZ-R010ELF" 2512 2720,3190 r180 top
R2 "CRCW060347R0JNEA" 0603 2870,2690 r90 bottom
R3 "CRCW060347R0JNEA" 0603 3610,2690 r90 bottom
R4 "CRCW08052R70JNEA" 0805_HV 2980,3893.2 r270 top
R5 "CRCW08052R70JNEA" 0805_HV 3780,3890 r270 top
R6 "CRCW06033R00JNEA" 0603 3010,2820 r0 bottom
R7 "CRCW06033R00JNEA" 0603 3470,2820 r180 bottom
R8 "CRCW060347R0JNEA" 0603 3120,2690 r90 bottom
R9 "CRCW060347R0JNEA" 0603 3360,2690 r270 bottom
R10 "CRCW08052R70JNEA" 0805_HV 3300,4000 r0 bottom
R11 "CRCW08052R70JNEA" 0805_HV 3460,4000 r180 bottom
R12 "CRCW060310R0JNEA" 0603 3730,2430 r0 top
R13 "CRCW060310R0JNEA" 0603 3450,2300 r0 bottom
R14 "CRCW04021K50FKED" 0402#1 3230,1700 r180 top
R15 "CRCW04021K50FKED" 0402#1 3130,1660 r270 top
R16 "CRCW04020000Z0ED" 0402#1 2700,1570 r0 top
R17 "CRCW040223K2FKED" 0402#1 3100,1730 r0 top
R18 "CRCW0402180KJNED" 0402#1 2880,1870 r270 top
R19 "CRCW0402180KJNED" 0402#1 2880,1760 r90 top
R20 "CRCW040216K5FKED" 0402#1 3230,1850 r0 top
R21 "CRCW040210K0JNED" 0402#1 3110,1820 r90 top
R22 "CRCW040210K0JNED" 0402#1 3160,1820 r90 top
R23 "CRCW040224K0JNED" 0402#1 2700,1510 r180 top
R24 "CRCW040233K2FKED" 0402#1 2840,1640 r0 top
R25 "CRCW040249K9FKED" 0402#1 2636.38,2720 r0 bottom
R26 "CRCW040249K9FKED" 0402#1 2516.38,2720 r180 bottom
R27 "CRCW040249K9FKED" 0402#1 2636.38,2670 r180 bottom
R28 "CRCW040249K9FKED" 0402#1 2516.38,2670 r0 bottom
R29 "CRCW040222R0JNED" 0402#1 2690,2050 r0 top
R30 "CRCW040222R0JNED" 0402#1 2690,2150 r0 top
R31 "CRCW04023K32FKED" 0402#1 2636.38,2620 r0 bottom
R32 "CRCW04023K32FKED" 0402#1 2516.38,2620 r180 bottom
R33 "CRCW040222R0JNED" 0402#1 2690,2250 r0 top
R34 "CRCW040222R0JNED" 0402#1 2690,2350 r0 top
R35 "CRCW040222R0JNED" 0402#1 2706.38,2600 r90 bottom
R36 "CRCW040222R0JNED" 0402#1 2446.38,2600 r90 bottom
R37 "CRCW040222R0JNED" 0402#1 4570,2390 r90 top
R38 "CRCW040222R0JNED" 0402#1 4180,2130 r180 top
R39 "CRCW04021K20JNED" 0402#1 3930,2380 r90 top
R40 "CRCW04021K20JNED" 0402#1 3880,2380 r90 top
R41 "CRCW04023R00JNED" 0402#1 4299.8,2821.3 r90 top
R42 "CRCW040251K0JNED" 0402#1 4109.8,2721.3 r180 top
R43 "CRCW060310R0JNEA" 0603 4449.8,2631.3 r270 top
R44 "CRCW040220K0FKED" 0402#1 4139.8,2861.3 r270 top
R45 "CRCW04029K10JNED" 0402#2 4459.8,2541.3 r180 top
R46 "CRCW0402200KJNED" 0402#1 4069.8,3311.3 r270 top
R47 "CRCW0402200KJNED" 0402#1 4069.8,3201.3 r270 top
R48 "CRCW04022K26FKED" 0402#1 4069.8,2971.3 r270 top
R49 "CRCW040251K0JNED" 0402#1 4119.8,3311.3 r270 top
R50 "CRCW040251K0JNED" 0402#1 4143.43,3231.3 r0 top
R51 "CRCW04027K50JNED" 0402#1 4169.8,3311.3 r270 top
R52 "CRCW0402475RFKED" 0402#1 3980,2380 r90 top
R53 "CRCW0402820RJNED" 0402#1 4159.8,2471.3 r180 top
R54 "CRCW0402806RFKED" 0402#1 4030,2380 r270 top
R55 "CRCW040251K0JNED" 0402#1 3570,1546.38 r90 top
R56 "CRCW04021K20JNED" 0402#1 3880,1760 r90 top
R57 "CRCW040251K0JNED" 0402#1 3930,1760 r270 top
R58 "CRCW040251K0JNED" 0402#1 3980,1760 r270 top
R59 "CRCW0402100KJNED" 0402#1 3660,1480 r180 top
R60 "CRCW04023K24FKED" 0402#1 4180,2080 r0 top
R61 "CRCW040210K0FKED" 0402#1 4320,2080 r180 top
R62 "CRCW040251K0JNED" 0402#1 4080,1550 r180 top
R63 "CRCW040251K0JNED" 0402#1 4310,1500 r0 top
R64 "CRCW04021K80JNED" 0402#1 3652.28,1666.38 r0 top
R65 "CRCW040249K9FKED" 0402#1 4550,2600 r0 top
R66 "CRCW040249K9FKED" 0402#1 4550,2540 r180 top
R67 "CRCW04026K80JNED" 0402#1 4080,2000 r180 top
R68 "CRCW0402487KFKED" 0402#1 4080,1940 r0 top
R69 "CRCW04021K00FKED" 0402#1 4550,2480 r0 top
R70 "CRCW0402100RJNED" 0402#1 4520,2390 r90 top
R71 "CRCW0402100KFKED" 0402#1 3970,1910 r0 top
R72 "CRCW04023K09FKED" 0402#1 4440,2410 r0 top
SW1 "TL1015AF160QG" SW_TL1015AF160QG 3320,1520 r0 top
TP1 "5002" Keystone5002 3480,1520 r90 top
U1 "SM72295MAX/NOPB" DW0028A_N 3330,2120 r90 top
U2 "ATL431BQDBZR" DBZ0003A_N 3005,1800 r0 top
U3 "LM5018MRX/NOPB" DDA0008B_N 4219.8,3051.3 r270 top
U4 "LM317LIPK" PK0003A_N 3950,2540 r180 top
U5 "SN74LVC1G175DCKR" DCK0006A_N 3673.62,1566.38 r180 top
U6 "LM2901VQD" D0014A_N 4190,1740 r270 top
U7 "LMT89DCKR" DCK0005A_N 3791.11,2579.95 r270 bottom
U8 "TL431QDBZT" DBZ0003A_N 4220,1970 r0 top

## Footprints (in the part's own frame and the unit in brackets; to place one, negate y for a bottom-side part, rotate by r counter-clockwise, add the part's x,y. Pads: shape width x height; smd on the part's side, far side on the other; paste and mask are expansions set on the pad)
0402#1 [mm] "0402 from SM-752 data"
  rect 0.8x0.6 smd: 1(-0.6,0) 2(0.6,0)
  silkscreen extent -1.22,-0.52 1.22,0.52, body extent -0.55,-0.3 0.55,0.3, height 0.6
0402#2 [mm] "0402 from SM-752 data"
  rect 0.8x0.6 smd: 1(-0.346,0.254) 2(0.854,0.254)
  silkscreen extent -1.22,-0.52 1.22,0.52, body extent -0.55,-0.3 0.55,0.3, height 0.6
0603 [mm] "0603 from SM-752 data"
  rect 1x0.95 smd: 1(-0.8,0) 2(0.8,0)
  silkscreen extent -1.52,-0.69 1.52,0.69, body extent -0.87,-0.47 0.87,0.47, height 1
0805_HV [mil] "0805 with 30mil clearance between pads"
  rect 50x63 smd: 1(-40,0) 2(40,0)
  silkscreen extent -74,-40 74,40, body extent -43,-29 43,29, height 57
1206_190 [mm] "1206_190"
  rect 1.1x1.6 smd: 1(-1.7,0) 2(1.7,0)
  silkscreen extent -0.9,-1 0.9,1, body extent -1.75,-0.95 1.75,0.95, height 1.9
2512 [mm] "Chip Resistor, Body 6.3x3.2mm, IPC Medium Density"
  rect 1.3x3.4 smd: 1(-2.95,0) 2(2.95,0)
  silkscreen extent -1.9,-1.6 1.9,1.6, body extent -3.22,-1.67 3.22,1.67, height 0.71
D0014A_N [mm] "SOIC, 14-Leads, Body 8.7x3.9mm, Pitch 1.27mm, IPC Medium Density"
  oval 1.45x0.6 smd: 1(-2.725,3.81) 2(-2.725,2.54) 3(-2.725,1.27) 4(-2.725,0) 5(-2.725,-1.27) 6(-2.725,-2.54) 7(-2.725,-3.81) 8(2.725,-3.81) 9(2.725,-2.54) 10(2.725,-1.27) 11(2.725,0) 12(2.725,1.27) 13(2.725,2.54) 14(2.725,3.81)
  silkscreen extent -3.3,-4.4 0.9,4.4, body extent -3.02,-4.32 3.02,4.32, height 1.6
DBZ0003A_N [mm] "SOT23, 3-Leads, Body 2.9x1.3mm, Pitch 0.95mm, Lead Span 2.4mm, IPC Medium Density"
  rrect17% 1x0.6 smd: 1(-1.2,0.95) 2(-1.2,-0.95) 3(1.2,0)
  silkscreen extent -1.65,-1.5 0.7,1.5, body extent -1.26,-1.46 1.26,1.46, height 0.98
DCK0005A_N [mm] "SOT353, 5-Leads, Body 2x1.3mm, Pitch 0.65mm, Lead Span 2.1mm, IPC Medium Density"
  rrect25% 0.85x0.4 smd: 1(-1.125,0.65) 2(-1.125,0) 3(-1.125,-0.65) 4(1.125,-0.65) 5(1.125,0.65)
  silkscreen extent -1.48,-1.02 0.55,1.1, body extent -1.14,-1 1.14,1, height 0.95
DCK0006A_N [mm] "SOT23, 6-Leads, Body 2x1.3mm, Pitch 0.65mm, Lead Span 2.1mm, IPC Medium Density"
  rrect25% 0.85x0.4 smd: 1(-1.125,0.65) 2(-1.125,0) 3(-1.125,-0.65) 4(1.125,-0.65) 5(1.125,0) 6(1.125,0.65)
  silkscreen extent -1.5,-1.09 0.51,1.09, body extent -1.14,-1 1.14,1, height 0.95
DDA0008B_N [mm] "SOIC, 8-Leads, Body 4.9x3.9mm, Pitch 1.27mm, Exposed Pad, IPC Medium Density"
  rrect100% 1.45x0.6 smd: 1(-2.725,1.905) 2(-2.725,0.635) 3(-2.725,-0.635) 4(-2.725,-1.905) 5(2.725,-1.905) 6(2.725,-0.635) 7(2.725,0.635) 8(2.725,1.905)
  rrect4% 2.41x3.1 smd: 9(0,0)
  silkscreen extent -3.3,-2.5 1.05,2.5, body extent -2.98,-2.45 2.98,2.45, height 1.55
DW0028A_N [mm] "SOIC, 28-Leads, Body 17.9x7.5mm, Pitch 1.27mm, IPC Medium Density"
  oval 1.9x0.6 smd: 1(-4.75,8.255) 2(-4.75,6.985) 3(-4.75,5.715) 4(-4.75,4.445) 5(-4.75,3.175) 6(-4.75,1.905) 7(-4.75,0.635) 8(-4.75,-0.635) 9(-4.75,-1.905) 10(-4.75,-3.175) 11(-4.75,-4.445) 12(-4.75,-5.715) 13(-4.75,-6.985) 14(-4.75,-8.255) 15(4.75,-8.255) 16(4.75,-6.985) 17(4.75,-5.715) 18(4.75,-4.445) 19(4.75,-3.175) 20(4.75,-1.905) 21(4.75,-0.635) 22(4.75,0.635) 23(4.75,1.905) 24(4.75,3.175) 25(4.75,4.445) 26(4.75,5.715) 27(4.75,6.985) 28(4.75,8.255)
  silkscreen extent -5.6,-9.05 2.9,9.05, body extent -5.16,-8.95 5.16,8.95, height 2.54
FCC_disclaimer [mil]
Fiducial6.4-20 [mil]
  round 25 smd mask+26.87: 1(0,0)
  Top Layer keep-out circle w46.37: c0,0 r19.68
IEC_HighVoltage_Small [mil]
  silkscreen extent -107,-88 107,97
Keystone5002 [mil] "For Keystone 500x miniature loop terminals"
  round 80 hole 40: 1(0,0)
  silkscreen extent -58,-58 58,58, body extent -49,-49 49,49, height 182
Pb-Free_Overlay_Small [mil]
  silkscreen extent -46,-46 46,46
PK0003A_N [mm] "SOT89, 3-Leads, Body 4.5x2.5mm, Pitch 1.5mm, IPC Medium Density"
  rrect14% 1.6x0.7 smd: 1(-1.9,1.5) 3(-1.9,-1.5)
  rrect14% 1.7x0.7 smd: 2(-1.85,0)
  Top Layer region: -1,0.35 -0.35,1 2.05,1 2.7,0.35 2.7,-0.35 2.05,-1 -0.35,-1 -1,-0.35 -1.2,-0.35 -1.2,0.35
  silkscreen extent -2.5,-2.3 1.6,2.3, body extent -2.13,-2.25 1.96,2.25, height 1.6
SOD-123 [mm] "On Semi recommended land pattern"
  rect 0.915x1.22 smd: 1(-1.637,0) 2(1.637,0)
  silkscreen extent -2.74,-1.17 2.03,1.17, body extent -1.93,-0.9 1.93,0.9, height 1.35
sod-323 [mm] "NXP recommended land pattern"
  rect 0.6x0.6 smd paste-0.05: 1(-1.1,0) 2(1.1,0)
  silkscreen extent -2.06,-0.86 1.53,0.86, body extent -1.3,-0.67 1.3,0.68, height 1.1
SOD-523 [mm] "NXP Semiconductor recommended land pattern, nominal STEP model"
  rect 0.8x0.6 smd paste-0.05: 1(-0.55,0) 2(0.55,0)
  silkscreen extent -1.6,-0.64 1.2,0.63, body extent -0.8,-0.4 0.8,0.4, height 0.72
SOT-26 [mm] "SOT23, 6-Leads, Body 3.1x3.0mm (max), Pitch 0.95mm, IPC Medium Density based on Diodes Inc ap02002.pdf rev 29"
  rect 1.05x0.6 smd: 1(-1.225,0.95) 2(-1.225,0) 3(-1.225,-0.95) 4(1.225,-0.95) 5(1.225,0) 6(1.225,0.95)
  silkscreen extent -0.3,-1.55 0.3,1.55, body extent -1.5,-1.5 1.5,1.5, height 1.3
SOT-323 [mm] "Zetex recommended land pattern.  March 2007"
  rect 0.8x0.6 smd: 1(-0.8,0.65) 2(-0.8,-0.65) 3(0.8,0)
  silkscreen extent -1.14,-1.22 0.77,1.22, body extent -1.13,-1.13 1.12,1.12, height 1.13
SW_TL1015AF160QG [mm] "E-Switch"
  rect 0.95x1.4 smd: 1(-2.1,0) 2(2.1,0)
  silkscreen extent -2,-1.5 2,1.5, body extent -2.3,-1.5 2.3,1.5, height 2
TP_SM_1MM [mm] "1mm Test Point, SMT"
  round 1 smd paste-0.5: 1(0,0)
TRANS_NexFET_Q5A [mm] "TI recommended land pattern (nominal) M0139-01"
  rect 0.75x0.675 smd paste-0.1 mask+0.051: 1(-2.776,1.917) 2(-2.776,0.639) 3(-2.776,-0.639) 4(-2.776,-1.917)
  rect 0.655x0.675 smd paste-0.1 mask+0.051: 5(2.776,-1.917) 6(2.776,-0.639) 7(2.776,0.639) 8(2.776,1.917)
  rect 4.295x4.51 smd paste-2.2 mask+0.051: 9(0.301,0)
  silkscreen extent -3.4,-2.8 3.4,2.8, body extent -3.05,-2.5 3.05,2.5, height 1.11
WCAP-ATUL_1000x2500 [mm] "TH, 2-Leads, Dia 10mm, Pin Spacing 5mm"
  rect 1.4x1.4 hole 0.9: 1(-2.5,0)
  round 1.4 hole 0.9: 2(2.5,0)
  silkscreen extent -5.25,-5.25 5.25,5.25, body extent -5.21,-5.24 5.24,5.24, height 26.51
WE-LQS_4012 [mm] "SMD, 2-Leads, Body 3.7x4mm"
  rect 1.5x3.6 smd: 1(-1.525,0) 2(1.525,0)
  silkscreen extent -1.95,-2.1 1.95,2.1, body extent -1.95,-2.1 1.95,2.1, height 1.2
WE-PMI_1008 [mm] "WURTH"
  rect 0.8x2.2 smd: 1(-1,0) 2(1,0)
  body extent -1.35,-1.1 1.35,1.1, height 1
WL-SMCW_GREEN [mm] "WURTH"
  rect 0.8x0.8 smd: 1(-0.8,0) 2(0.8,0)
  silkscreen extent -1.9,-0.8 1.2,0.8, body extent -0.85,-0.45 0.85,0.45, height 0.8
WL-SMCW_RED [mm] "WURTH"
  rect 0.8x0.8 smd: 1(-0.8,0) 2(0.8,0)
  silkscreen extent -1.9,-0.8 1.2,0.8, body extent -0.85,-0.45 0.85,0.45, height 0.8
Wurth_61030421121 [mm] "Header, 2.54mm, 2x2, Gold, TH"
  rect 3.1x1 smd: 1(-2.7,1.27) 2(2.7,1.27) 3(-2.7,-1.27) 4(2.7,-1.27)
  silkscreen extent -2.54,-2.54 2.54,2.92, body extent -3.75,-2.54 3.75,2.54, height 9.6
Wurth_61031221121 [mm] "Header, 2.54mm, 6x2, Gold, TH"
  rect 3.1x1 smd: 1(-2.7,6.35) 2(2.7,6.35) 3(-2.7,3.81) 4(2.7,3.81) 5(-2.7,1.27) 6(2.7,1.27) 7(-2.7,-1.27) 8(2.7,-1.27) 9(-2.7,-3.81) 10(2.7,-3.81) 11(-2.7,-6.35) 12(2.7,-6.35)
  silkscreen extent -2.54,-7.62 2.54,8, body extent -3.75,-7.62 3.75,7.62, height 9.6
Wurth_691311500002 [mm] "Header (Shrouded), 5.08mm, 2x1, TH"
  rect 2.1x2.1 hole 1.6: 1(-2.54,0)
  round 2.1 hole 1.6: 2(2.54,0)
  silkscreen extent -5.5,-4.7 5.08,3.8, body extent -5.06,-4.7 5.1,3.8, height 12
Wurth_691311500103 [mm] "Header (Shrouded), 5.08mm, 3x1, TH"
  rect 2.1x2.1 hole 1.6: 1(-5.08,0)
  round 2.1 hole 1.6: 2(0,0) 3(5.08,0)
  Top Layer lines w0.1: 0.25,0 -0.25,0 ; 0,0.25 0,-0.25
  silkscreen extent -9.1,-4.7 8.62,3.8, body extent -8.62,-4.7 8.62,3.8, height 12

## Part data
C1 C2: "CAP, AL, 100 µF, 100 V, +/- 20%, 0.2 ohm, TH"
C3 C4 C5 C40: "CAP, CERM, 3.3 µF, 100 V, +/- 20%, X7S, 1206_190"
C6 C7: "CAP, CERM, 0.1 µF, 100 V, +/- 10%, X7R, 0805"
C8 C9 C14 C15: "CAP, CERM, 2200 pF, 100 V, +/- 5%, X7R, 0603"
C10 C12: "CAP, CERM, 1 µF, 100 V, +/- 10%, X7S, 0805"
C11 C13: "CAP, CERM, 0.01 µF, 100 V, +/- 10%, X7R, 0603"
C16 C24 C25 C46: "CAP, CERM, 0.01 µF, 16 V, +/- 10%, X7R, 0402"
C17 C19: "CAP, CERM, 1 µF, 16 V, +/- 20%, X5R, 0603"
C18 C36 C39 C44 C48: "CAP, CERM, 0.1 µF, 25 V, +/- 20%, X7R, 0402"
C20: "CAP, CERM, 4700 pF, 100 V, +/- 10%, X7R, 0402"
C21 C22 C23 C26 C27 C28 C29 C30 C31 C32 C33 C45 C47 C51: "CAP, CERM, 100 pF, 50 V, +/- 10%, X7R, 0402"
C34: "CAP, CERM, 3300 pF, 100 V, +/- 10%, X7R, 0603"
C35: "CAP, CERM, 0.1 µF, 100 V, +/- 10%, X7R, 0603"
C37 C38: "CAP, CERM, 4.7 µF, 25 V, +/- 10%, X5R, 0603"
C41 C42 C43: "CAP, CERM, 1 µF, 16 V, +/- 10%, X5R, 0603"
C49: "CAP, CERM, 1000 pF, 25 V, +/- 10%, X7R, 0402"
C50: "CAP, CERM, 0.1 µF, 16 V, +/- 20%, X5R, 0402"
D1 D2 D5 D6 D9: "Diode, Ultrafast, 100 V, 0.25 A, SOD-323"
D3 D4: "Diode, Zener, 91 V, 500 mW, SOD-123"
D7 D8 D13: "LED, Red, SMD"
D10 D11: "LED, Green, SMD"
D12: "Diode, Zener, 3.9 V, 300 mW, SOD-523"
D14: "Diode, Switching, 75 V, 0.15 A, SOT-323"
"DANGER HIGH VOLTAGE1" "DANGER HIGH VOLTAGE!1": library part IEC_HighVoltage, "IEC 61010-1 High Voltage Warning"
FID1 FID2 FID3 FID4 FID5 FID6: "Fiducial mark.  There is nothing to buy or mount."
I_CS1: library part TP_SM_1MM, "1mm Test Point, SMT"
J1 J4: "Header, 2.54mm, 2x2, Gold, SMT"
J2: "Header, 2.54mm, 6x2, Gold, SMT"
J3: "Header (Shrouded), 5.08mm, 3x1, Tin, TH"
J5: "Header (Shrouded), 5.08mm, 2x1, Tin, TH"
L1: "Inductor, Wirewound, Ferrite, 100 µH, 0.35 A, 1.697 ohm, SMD"
L2: "Inductor, Shielded Drum Core, Metal Composite, 10 µH, 0.35 A, 0.7 ohm, SMD"
Logo1: library part Pb-Free
Logo2: library part FCC_disclaimer, "FCC_disclaimer"
Q1 Q2 Q3 Q4: "MOSFET, N-CH, 100 V, 10 A, SON 5x6mm"
Q5: library part "DMMT5551-7-F, Diodes Inc.", "Transistor, Dual NPN, 160 V, 0.2 A, SOT-26"
R1: "RES, 0.01, 1%, 3 W, 2512"
R2 R3 R8 R9: "RES, 47, 5%, 0.1 W, 0603"
R4 R5 R10 R11: "RES, 2.7, 5%, 0.125 W, 0805"
R6 R7: "RES, 3.0, 5%, 0.1 W, 0603"
R12 R13 R43: "RES, 10, 5%, 0.1 W, 0603"
R14 R15: "RES, 1.50 k, 1%, 0.063 W, 0402"
R16: "RES, 0, 5%, 0.063 W, 0402"
R17: "RES, 23.2 k, 1%, 0.063 W, 0402"
R18 R19: "RES, 180 k, 5%, 0.063 W, 0402"
R20: "RES, 16.5 k, 1%, 0.063 W, 0402"
R21 R22: "RES, 10 k, 5%, 0.063 W, 0402"
R23: "RES, 24 k, 5%, 0.063 W, 0402"
R24: "RES, 33.2 k, 1%, 0.063 W, 0402"
R25 R26 R27 R28 R65 R66: "RES, 49.9 k, 1%, 0.063 W, 0402"
R29 R30 R33 R34 R35 R36 R37 R38: "RES, 22, 5%, 0.063 W, 0402"
R31 R32: "RES, 3.32 k, 1%, 0.063 W, 0402"
R39 R40 R56: "RES, 1.2 k, 5%, 0.063 W, 0402"
R41: "RES, 3.0, 5%, 0.063 W, 0402"
R42 R49 R50 R55 R57 R58 R62 R63: "RES, 51 k, 5%, 0.063 W, 0402"
R44: "RES, 20.0 k, 1%, 0.063 W, 0402"
R45: "RES, 9.1 k, 5%, 0.063 W, 0402"
R46 R47: "RES, 200 k, 5%, 0.063 W, 0402"
R48: "RES, 2.26 k, 1%, 0.063 W, 0402"
R51: "RES, 7.5 k, 5%, 0.063 W, 0402"
R52: "RES, 475, 1%, 0.063 W, 0402"
R53: "RES, 820, 5%, 0.063 W, 0402"
R54: "RES, 806, 1%, 0.063 W, 0402"
R59: "RES, 100 k, 5%, 0.063 W, 0402"
R60: "RES, 3.24 k, 1%, 0.063 W, 0402"
R61: "RES, 10.0 k, 1%, 0.063 W, 0402"
R64: "RES, 1.8 k, 5%, 0.063 W, 0402"
R67: "RES, 6.8 k, 5%, 0.063 W, 0402"
R68: "RES, 487 k, 1%, 0.063 W, 0402"
R69: "RES, 1.00 k, 1%, 0.063 W, 0402"
R70: "RES, 100, 5%, 0.063 W, 0402"
R71: "RES, 100 k, 1%, 0.063 W, 0402"
R72: "RES, 3.09 k, 1%, 0.063 W, 0402"
SW1: "Switch, Tactile, SPST-NO, 0.05A, 12V, SMT"
TP1: "Test Point, Miniature, White, TH"
U1: "Photovoltaic Full Bridge Driver, DW0028A"
U2: "2.5V Low Iq Adjustable Precision Shunt Regulator, DBZ0003A"
U3: "100V, 300mA Constant On-Time Synchronous Buck Regulator, DDA0008B"
U4: "3-Terminal Adjustable Regulator, PK0003A"
U5: "SINGLE D-TYPE FLIP-FLOP WITH ASYNCHRONOUS CLEAR, DCK0006A"
U6: "Quad Comparator, D0014A"
U7: "2.4V, 10µA, SC70, DSBGA Temperature Sensor, DCK0005A"
U8: "Adjustable Precision Shunt Regulator, 34 ppm / degC, 100 mA, -40 to 125 degC, 3-pin SOT-23 (DBZ), Green (RoHS & no Sb/Br)"

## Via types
v1: diameter 20, hole 10, Top Layer to Bottom Layer, 355 vias
v2: diameter 40, hole 20, Top Layer to Bottom Layer, 7 vias
v3: diameter 240, hole 140, Top Layer to Bottom Layer, 4 vias
v4: diameter 25.98, hole 12.99, Top Layer to Bottom Layer, tented top, 4 vias

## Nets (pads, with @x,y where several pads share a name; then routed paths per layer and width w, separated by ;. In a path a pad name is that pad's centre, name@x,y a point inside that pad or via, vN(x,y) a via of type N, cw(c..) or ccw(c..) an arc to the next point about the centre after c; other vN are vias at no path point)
+3V3: C24.1 C43.1 C48.1 D14.2 J4.4 Q5.5 R12.2 R39.2 R40.2 R52.2 R53.2 U4.2 U7.4 | length 4036.2
  Top Layer w20: Q5.5@2888.23,1540 v1(2930,1540) 2953.62,1540 C24.1@2960,1533.62 ; R12.2@3771.5,2430 3781.5,2420 3880,2420 ; v2(3880,2540) 3880,2420 ; R52.2@3980,2403.62 R39.2@3930,2403.62 R40.2@3880,2403.62 3880,2420
  Top Layer w30: v2(3880,2540) U4.2@4022.83,2540 4117.51,2540
  Mid Layer w20: v1(2930,1540) 3020,1450 3510,1450 3570,1510 3600,1510 3880,1790 v2(3880,2540) ; v2(4145.53,2527.27) 4550,2931.74 v2(4550,3400)
  Bottom Layer w20: C48.1@3813.62,2480 3816.7,2483.08 U7.4@3816.7,2535.66 3821.05,2540 v2(3880,2540) ; v2(4145.53,2527.27) 4208.6,2464.19 D14.2@4454.25,2464.19
+4V: C46.1 D12.1 R55.2 R56.1 U5.3 U5.5 | length 432.1
  Top Layer w16: R55.2@3570,1570 3573.62,1566.38 U5.5@3629.33,1566.38 3662.65,1566.38 3688.24,1591.97 U5.3@3717.91,1591.97 3729.21,1591.97 3747.24,1610 C46.1@3772.65,1610 D12.1@3834.62,1610
  Top Layer w20: D12.1@3832.65,1608.03 3834.62,1610 3880,1655.38 R56.1@3880,1736.38
+12V: C25.1 C38.1 C39.1 C42.1 C44.1 D9.2 J4.2 R13.2 R23.2 R43.2 R45.2 R56.2 R57.1 R58.1 R59.2 R67.2 U4.3 U6.3 | length 5339.6
  Top Layer w20: C25.1@2623.62,1510 v1(2650,1510) R23.2@2676.38,1510 ; v1(3600,1470) 3620,1470 R59.2@3626.38,1476.38 ; R56.2@3880,1783.62 R58.1@3980,1783.62 ; C44.1@3973.62,1840 v1(3973.62,1815) 3973.62,1790 R58.1@3980,1783.62 ; v1(4030,2000) R67.2@4056.38,2000 ; U6.3@4240,1847.28 4240,1804.45 4219.17,1783.62 R58.1@3980,1783.62
  Mid Layer w20: v1(3600,1470) 3628.62,1470 v1(3973.62,1815) 4000,1841.38 4000,1970 v1(4030,2000)
  Mid Layer w30: v2(4410,2560) 4650,2800 v2(4650,3400)
  Bottom Layer w20: v1(2650,1510) 2665.13,1494.87 3134.87,1494.87 3684.33,2044.33 3684.33,2220
  Bottom Layer w30: R13.2@3481.5,2300 3604.33,2300 3684.33,2220 4090,2220 ; v1(4030,2000) 4090,2060 4090,2220 ; v2(4410,2560) 4310,2660 v2(4150,2660) 4090,2600 4090,2220
/FAULT: D8.1 U1.15 | length 136
  Top Layer w20: U1.15@3655,2307.01 3655,2325 3690,2360 D8.1@3758.5,2360
BIN: R22.2 U1.4 | length 84.4
  Top Layer w20: R22.2@3155,1848.62 U1.4@3155,1932.99
BOUT: R38.2 R60.1 U1.11 | length 786.9
  Top Layer w20: U1.11@3505,1932.99 3505,1975 3540,2010 3930,2010 4000,2080 R60.1@4156.38,2080 R38.2@4156.38,2130
DC_LINK: D14.3 R37.2 R66.1 R69.2 | length 189
  Top Layer w20: R37.2@4570,2413.62 4573.62,2417.24 v1(4573.62,2450) R69.2@4573.62,2480 R66.1@4573.62,2540
  Bottom Layer w20: D14.3@4517.24,2438.6 4528.64,2450 v1(4573.62,2450)
FB: C36.2 R44.1 R48.2 U3.5 | length 182.5
  Top Layer w20: R48.2@4069.8,2947.68 U3.5@4141.14,2947.68 ; C36.2@4089.8,2884.92 R44.1@4139.8,2884.92 4144.8,2889.92 U3.5@4144.8,2944.02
